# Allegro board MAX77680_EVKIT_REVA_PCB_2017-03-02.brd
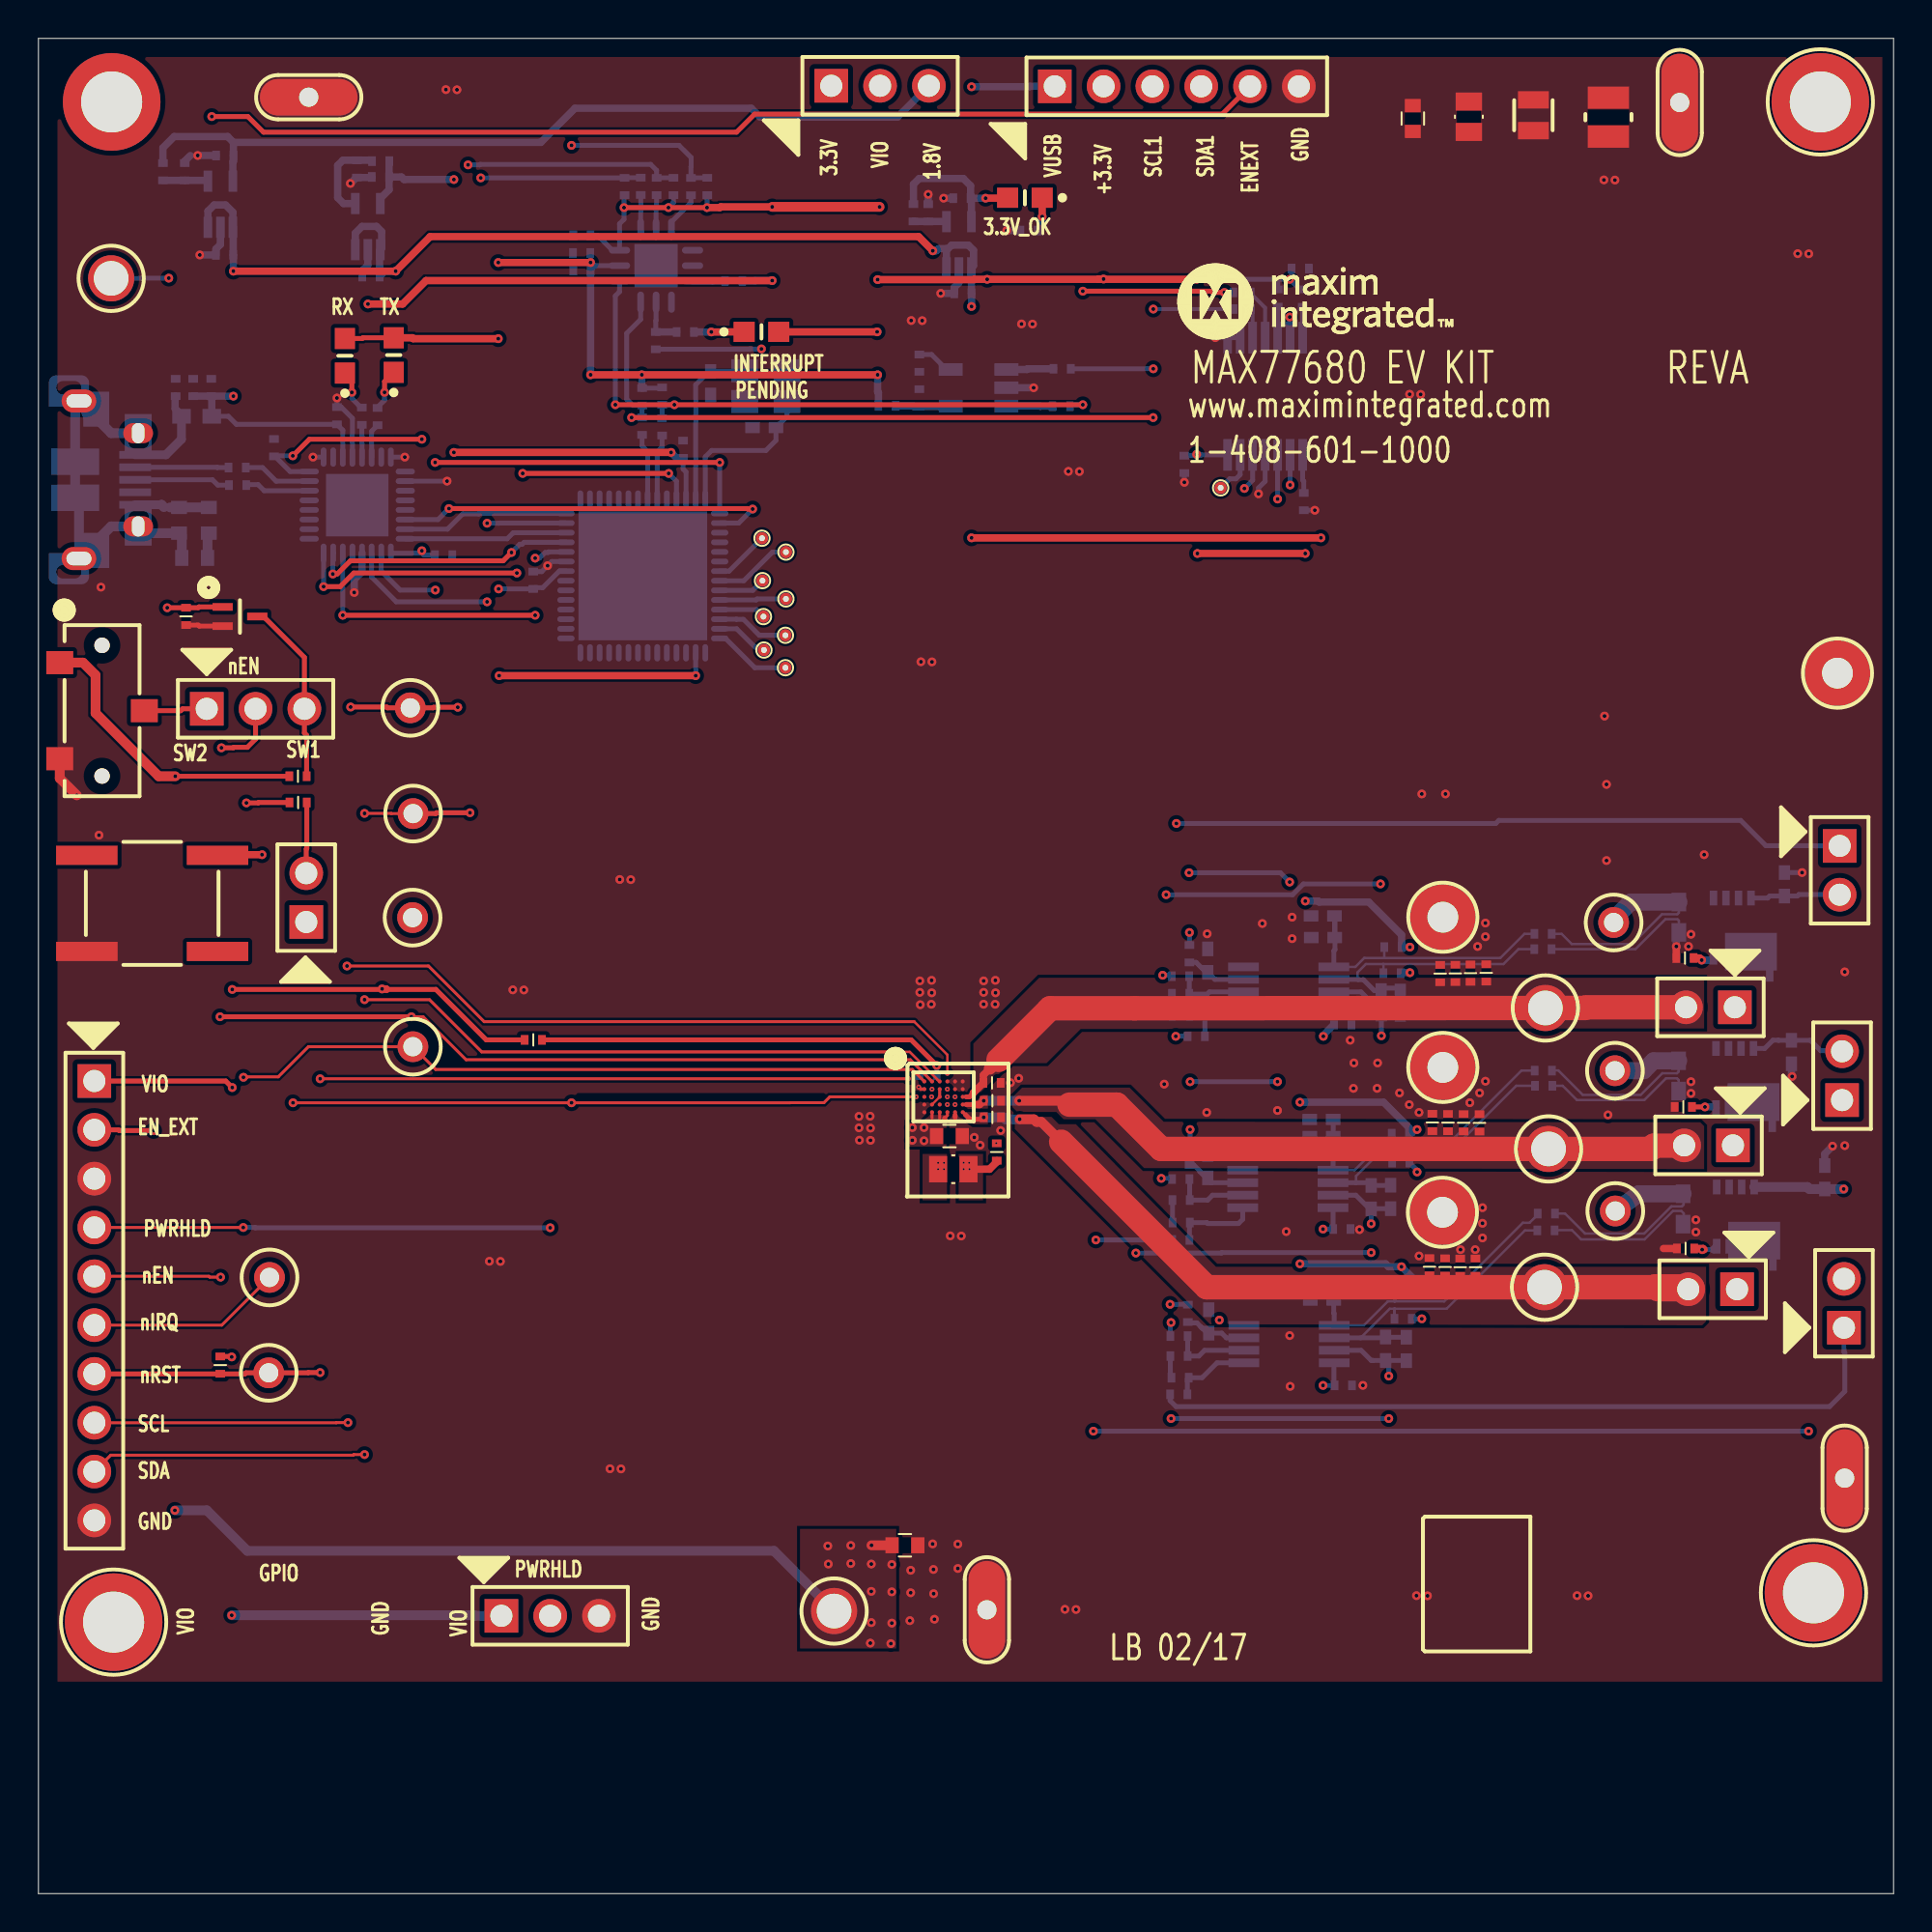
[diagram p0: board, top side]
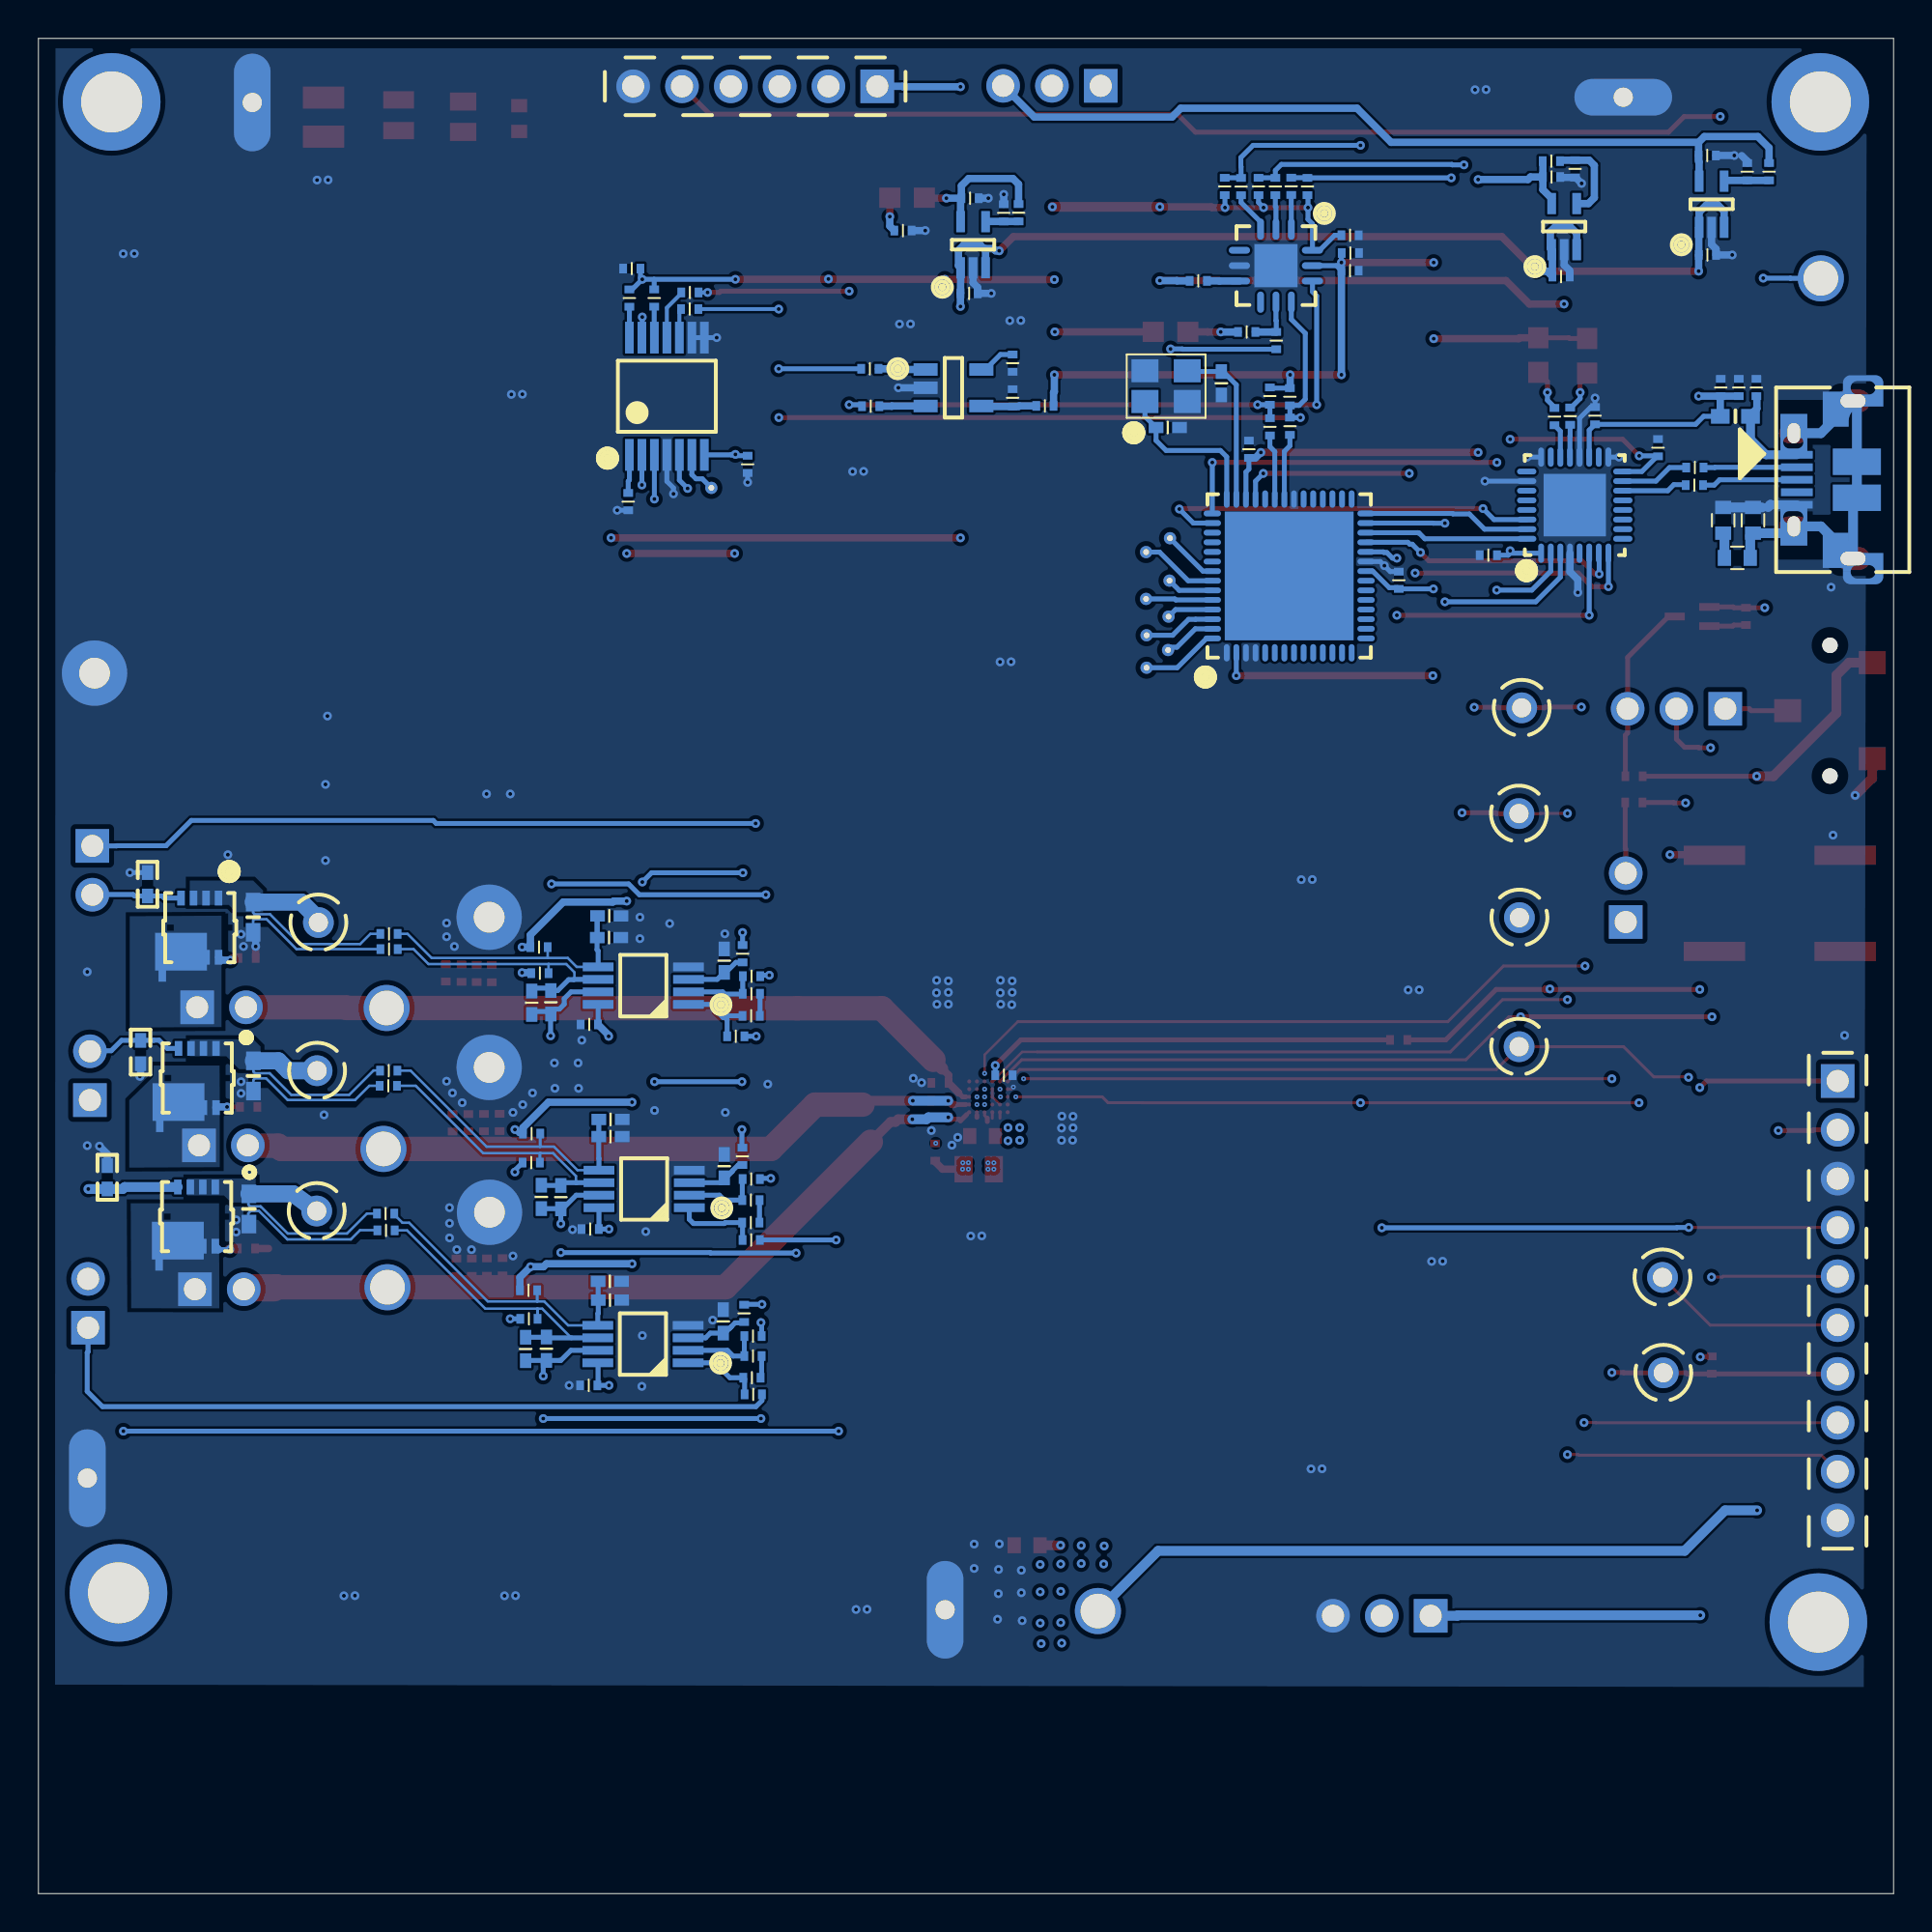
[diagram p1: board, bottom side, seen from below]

Outline 96.52 x 96.52 mm; copper layers: TOP, INTERNAL2, INTERNAL3, BOTTOM. Coordinates in mm from the lower left corner of the outline.
Outline path: 0,96.52 0,0 96.52,0 96.52,96.52 0,96.52

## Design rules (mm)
constraint set DEFAULT: min track width 0.102
net group NIRQ: nets NIRQ UNNAMED_4_EKRESSMD_I87_1
net group NIRQ1: nets NIRQ1 UNNAMED_4_EKRESSMD_I190_2
net group UNNAMED_4_10103592-0001LF_I2_2: nets UNNAMED_4_10103592-0001LF_I2_2 UNNAMED_4_EKRESSMD_I15_2
net group UNNAMED_4_10103592-0001LF_I2_3: nets UNNAMED_4_10103592-0001LF_I2_3 UNNAMED_4_EKRESSMD_I16_2
net group UNNAMED_4_10103592-0001LF_I2_SHIELD10: nets UNNAMED_4_10103592-0001LF_I2_SHIELD10 UNNAMED_4_EKCAPNP_I29_1
net group UNNAMED_4_EKRESSMD_I17_1: nets UNNAMED_4_EKRESSMD_I17_1 UNNAMED_4_EKRESSMD_I17_2
net group UNNAMED_4_EKRESSMD_I18_1: nets UNNAMED_4_EKRESSMD_I18_1 UNNAMED_4_EKRESSMD_I18_2
net group VUSB: nets UNNAMED_4_10103592-0001LF_I2_1 VUSB
net group SCL: nets SCL SDA UNNAMED_4_EKRESSMD_I153_1 UNNAMED_4_EKRESSMD_I154_1 UNNAMED_4_EKRESSMD_I171_2 VIO
net group SCL1: nets SCL1 UNNAMED_4_EKRESSMD_I109_1 UNNAMED_6_24AA02_I452_SCL
net group SDA1: nets SDA1 UNNAMED_4_EKRESSMD_I113_1 UNNAMED_6_24AA02_I452_SDA

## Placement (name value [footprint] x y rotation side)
C1  22UF  [CAPC1608X90L]  47.4 39.41 0 top
C2  0.01UF  [CAPC1005X50L]  75.33 47.9 270 top
C4  3300PF  [0402]  49.86 38.58 270 top
C6  10UF  [CAPC1005X50L]  49.63 40.39 180 top
C8  10UF  [CAPC1005X50L]  49.63 41.25 180 top
C9  10UF  [CAPC1005X50L]  49.61 42.18 180 top
C12  1UF  [CAPC1005X50L]  46.29 42.57 0 bottom
C14  0.1UF  [CAPC1005X50L]  45.83 77.82 270 bottom
C19  OPEN  [CAPC1005X50L]  72.93 47.87 270 top
C20  10UF  [CAPC1005X50L]  72.53 40.12 270 top
C21  OPEN  [CAPC1005X50L]  73.72 47.88 270 top
C22  OPEN  [CAPC1005X50L]  73.34 40.11 270 top
C24  OPEN  [CAPC1005X50L]  72.37 32.61 270 top
C26  OPEN  [CAPC1005X50L]  73.19 32.6 270 top
C27  0.1UF  [CAPC1005X50L]  74.51 47.89 270 top
C28  0.1UF  [CAPC1005X50L]  74.15 40.1 270 top
C29  0.1UF  [CAPC1005X50L]  73.97 32.59 270 top
C30  22UF  [CAPC1608X90L]  45.08 18.12 0 top
C31  0.01UF  [CAPC1005X50L]  74.97 40.1 270 top
C32  0.01UF  [CAPC1005X50L]  74.77 32.59 270 top
C108  0.1UF  [CAPC1005X50L]  15.53 76.89 270 bottom
C110  1UF  [CAPC1005X50L]  9.68 85.26 0 bottom
C111  1UF  [CAPC1005X50L]  9.69 90.43 0 bottom
C112  1UF  [CAPC1005X50L]  17.3 84.13 0 bottom
C113  1UF  [CAPC1005X50L]  17.8 89.31 0 bottom
C114  0.47UF  [CAPC1608X90L]  8.86 71.45 90 bottom
C115  1UF  [CAPC1005X50L]  28.28 84.44 0 bottom
C118  1UF  [CAPC1005X50L]  48.1 83.26 0 bottom
C120  1UF  [CAPC1005X50L]  28.28 86.28 0 bottom
C150  0.1UF  [CAPC1005X50L]  25.74 68.33 90 bottom
C151  0.1UF  [CAPC1005X50L]  33.54 75.15 90 bottom
C152  15PF  [0402#2]  37.76 76.28 0 bottom
C153  15PF  [0402#2]  34.97 78.58 90 bottom
C154  4.7UF  [CAPC1005X50L]  8.05 78.36 270 bottom
C155  0.1UF  [CAPC1005X50L]  7.14 78.36 90 bottom
C156  0.1UF  [CAPC1005X50L]  12.26 75.23 270 bottom
C157  0.1UF  [CAPC1005X50L]  28.26 85.36 0 bottom
C158  1UF  [CAPC1005X50L]  48.05 88.21 0 bottom
C159  0.1UF  [CAPC1005X50L]  21.08 69.63 0 bottom
C200  4700PF  [0402#2]  60.84 48.54 270 bottom
C201  1000PF  [CAPC1005X50L]  59.43 46.82 180 bottom
C202  0.1UF  [CAPC1005X50L]  67.86 45.22 0 bottom
C203  18PF  [0402#2]  69.86 46.37 90 bottom
C204  18PF  [0402#2]  66.83 49.74 0 bottom
C206  1000PF  [CAPC1005X50L]  59.45 36.08 180 bottom
C207  0.1UF  [CAPC1005X50L]  67.81 34.57 0 bottom
C208  18PF  [0402#2]  66.76 39.38 0 bottom
C209  18PF  [0402#2]  70.35 36.25 90 bottom
C211  1000PF  [CAPC1005X50L]  59.34 27.97 180 bottom
C212  0.1UF  [CAPC1005X50L]  67.89 26.44 0 bottom
C213  18PF  [0402#2]  70.09 28.35 90 bottom
C214  18PF  [0402#2]  66.78 30.88 0 bottom
C221  0.1UF  [CAPC1005X50L]  65.65 84.55 180 bottom
C222  0.1UF  [CAPC1005X50L]  59.62 74.36 90 bottom
C223  0.1UF  [CAPC1005X50L]  65.83 72.42 90 bottom
C239  1UF  [CAPC1005X50L]  85.67 48.67 0 top
C240  1UF  [CAPC1005X50L]  85.58 40.93 0 top
C241  1UF  [CAPC1005X50L]  85.7 33.56 0 top
C248  4700PF  [0402#2]  60.84 37.85 270 bottom
C250  4700PF  [0402#2]  60.89 29.77 270 bottom
D100  LTST-C190YKT  [LEDC1608X80M]  18.48 80.05 90 top
D101  LTST-C190YKT  [LEDC1608X80M]  15.94 80.01 90 top
D102  LTST-C190CKT  [LEDC1608X80M]  51.32 88.23 180 top
D103  LTST-C190CKT  [LEDC1608X80M]  37.62 81.25 0 top
EN_EXT  N/A  [TP_C240H180]  3.78 84.04 0 top
FB100  220  [0603#2]  8.23 76.86 0 bottom
GND1  N/A  [TP_C340H160]  93.6 63.5 90 top
GND2  MAXIMPAD  [EVK_MAXIMPAD]  49.35 14.77 270 top
GND3  MAXIMPAD  [EVK_MAXIMPAD]  14.06 93.46 0 top
GND4  MAXIMPAD  [EVK_MAXIMPAD]  85.39 93.19 270 top
GND5  N/A  [TP_C340H160]  73.05 35.45 0 top
GND6  N/A  [TP_C340H160]  73.07 42.98 0 top
GND7  N/A  [TP_C340H160]  73.07 50.8 0 top
GND8  MAXIMPAD  [EVK_MAXIMPAD]  93.98 21.61 90 top
J2  PBC10SAAN  [SULLINS_PXC10SAAN]  2.91 42.28 270 top
J4  TSW-103-07-T-S  [SAMTEC_TSW-103-07-T-S]  24.09 14.45 0 top
J5  TSW-103-07-T-S  [SAMTEC_TSW-103-07-T-S]  8.76 61.64 0 top
J6  10103592-0001LF  [FCI_10103592-0001LF]  2.11 73.56 90 bottom
J8  TSW-102-07-T-S  [SAMTEC_TSW-102-07-X-S]  13.93 50.55 90 top
J100  PBC06SAAN  [SULLINS_PXC06SAAN]  52.88 94.03 0 top
J101  TSW-103-07-T-S  [SAMTEC_TSW-103-07-T-S]  41.25 94.06 0 top
J200  TSW-102-07-T-S  [SAMTEC_TSW-102-07-X-S]  93.72 54.51 270 top
J201  TSW-102-07-T-S  [SAMTEC_TSW-102-07-X-S]  88.26 46.11 180 top
J202  TSW-102-07-T-S  [SAMTEC_TSW-102-07-X-S]  93.84 41.28 90 top
J203  TSW-102-07-T-S  [SAMTEC_TSW-102-07-X-S]  88.16 38.93 180 top
J204  TSW-102-07-T-S  [SAMTEC_TSW-102-07-X-S]  93.94 29.44 90 top
J205  TSW-102-07-T-S  [SAMTEC_TSW-102-07-X-S]  88.38 31.44 180 top
L1  1.5UH  [0805]  47.6 37.69 180 top
L2  0.47UH  [0603]  71.51 92.35 90 top
L3  2.2UH  [0805]  74.42 92.45 90 top
L4  2.2UH  [IND_2016]  77.78 92.53 90 top
L5  2.2UH  [IND_2520]  81.69 92.43 90 top
NEN  N/A  [TP_180P120D460H]  19.47 50.78 0 top
NIRQ  N/A  [TP_180P120D460H]  12.02 32.06 0 top
NOREF  -  []  49.43 150.22 0 top
NOREF#2  -  []  61.29 82.75 0 top
NOREF#3  -  [unnamed#2]  92.35 15.65 0 top
NOREF#4  -  [unnamed#2]  3.81 93.22 0 top
NOREF#5  -  []  -23.98 89.1 0 top
NOREF#6  -  [unnamed#2]  92.71 93.22 0 top
NOREF#7  -  []  108.1 89.1 0 top
NOREF#8  -  [unnamed#2]  3.91 14.12 0 top
NOREF#9  -  []  108.1 -9.96 0 top
NOREF#10  -  []  12.75 1.73 0 top
NRST  N/A  [TP_180P120D460H]  11.98 27.09 0 top
PO0  N/A  [TP_C25H12]  37.65 70.52 90 top
PO1  N/A  [TP_C25H12]  38.89 69.8 90 top
PO2  N/A  [TP_C25H12]  37.67 68.31 90 top
PO3  N/A  [TP_C25H12]  38.89 67.36 90 top
PO4  N/A  [TP_C25H12]  37.72 66.44 90 top
PO5  N/A  [TP_C25H12]  38.86 65.47 90 top
PO6  N/A  [TP_C25H12]  37.75 64.7 90 top
PO7  N/A  [TP_C25H12]  38.86 63.78 90 top
PWRHLD  N/A  [TP_180P120D460H]  19.48 44.06 0 top
Q1  FDY300NZ  [SOT50P160X90-3M]  10.48 66.44 0 top
Q200  IRFHM8337TRPBF  [TRAN_IRF_PQFN8_SINGLE_B]  88.13 50.26 270 bottom
Q201  IRFHM8337TRPBF  [TRAN_IRF_PQFN8_SINGLE_B]  88.26 42.43 270 bottom
Q202  IRFHM8337TRPBF  [TRAN_IRF_PQFN8_SINGLE_B]  88.29 35.22 270 bottom
R1  100K  [RESC1005X50L]  7.61 89.59 90 bottom
R2  10K  [0402]  13.5 58.13 180 top
R3  100K  [RESC1005X50L]  7.68 66.45 270 top
R10  10K  [0402]  9.46 27.5 270 top
R14  100K  [RESC1005X50L]  34.8 88.82 270 bottom
R16  150  [0402]  13.51 56.77 0 top
R17  0  [RESC1005X50L]  25.75 44.42 180 top
R100  4.7K  [RESC1005X50L]  32.45 77.91 90 bottom
R103  22  [RESC1005X50L]  10.36 73.28 0 bottom
R107  2.2K  [RESC1005X50L]  33.04 88.82 90 bottom
R108  2.2K  [RESC1005X50L]  30.5 88.82 90 bottom
R109  100  [RESC1005X50L]  16.83 76.87 90 bottom
R110  470  [0402]  51.54 86.52 180 bottom
R111  100  [RESC1005X50L]  17.64 76.84 90 bottom
R115  100K  [RESC1005X50L]  8.99 78.36 90 bottom
R118  4.7K  [RESC1005X50L]  31.41 77.88 90 bottom
R122  1M  [RESC1608X90L]  7.32 71.45 90 bottom
R123  22  [RESC1005X50L]  10.34 74.19 0 bottom
R135  0  [RESC1005X50L]  31.34 88.83 90 bottom
R136  0  [RESC1005X50L]  32.16 88.82 90 bottom
R142  0  [RESC1608X90L]  8.13 69.49 0 bottom
R143  0  [RESC1005X50L]  36.17 83.91 180 bottom
R148  0  [RESC1005X50L]  32.45 76.31 90 bottom
R150  22  [RESC1005X50L]  33.95 88.81 90 bottom
R152  0  [RESC1005X50L]  32.12 80.8 90 bottom
R155  0  [RESC1005X50L]  31.41 76.34 90 bottom
R156  105K  [0402]  17.81 90.14 180 bottom
R157  100K  [RESC1005X50L]  16.57 89.73 270 bottom
R158  169K  [0402]  45.53 87.45 270 bottom
R159  100K  [RESC1005X50L]  46.29 87.45 90 bottom
R160  47.5K  [0402]  6.48 89.59 270 bottom
R161  470  [0402]  33.66 81.25 180 bottom
R162  0  [RESC1005X50L]  53.26 79.33 180 bottom
R163  0  [RESC1005X50L]  44.15 77.4 180 bottom
R164  0  [RESC1005X50L]  53.22 77.39 0 bottom
R165  0  [RESC1005X50L]  45.83 79.63 270 bottom
R201  100  [0402]  59.44 45.67 0 bottom
R202  680  [0402]  59.42 47.73 180 bottom
R203  20K  [0402]  59.88 48.9 270 bottom
R204  0  [RESC1005X50L]  60.24 44.6 180 bottom
R205  4.99K  [0402#2]  70.85 46.35 90 bottom
R206  4.99K  [0402#2]  66.82 50.86 0 bottom
R207  1K  [RESC1005X50L]  78.28 49.93 0 bottom
R208  1K  [RESC1005X50L]  78.28 49.14 0 bottom
R210  1M  [0402#2]  90.84 52.51 270 bottom
R211  1  [0603#2]  85.35 50.8 270 bottom
R214  100K  [RESC1005X50L]  65.78 83.01 90 bottom
R222  100  [0402]  59.46 34.91 0 bottom
R223  680  [0402]  59.43 37.17 180 bottom
R224  20K  [0402]  59.89 38.36 270 bottom
R225  0  [RESC1005X50L]  59.44 34.01 180 bottom
R226  4.99K  [0402#2]  66.75 40.28 0 bottom
R228  4.99K  [0402#2]  69.34 36.23 90 bottom
R229  1K  [RESC1005X50L]  78.3 42.82 0 bottom
R230  1K  [RESC1005X50L]  78.32 42.03 0 bottom
R231  1M  [0402#2]  91.21 43.78 90 bottom
R233  1  [0603#2]  85.34 42.54 270 bottom
R235  100  [0402]  59.4 26.84 0 bottom
R236  680  [0402]  59.34 29 180 bottom
R237  20K  [0402]  59.8 30.19 270 bottom
R238  0  [RESC1005X50L]  59.33 25.97 180 bottom
R239  4.99K  [0402#2]  71.17 28.33 90 bottom
R240  4.99K  [0402#2]  66.79 31.86 0 bottom
R242  1K  [RESC1005X50L]  78.46 35.38 0 bottom
R243  1K  [RESC1005X50L]  78.44 34.5 0 bottom
R244  1M  [0402#2]  92.94 37.27 270 bottom
R245  1  [0603#2]  85.57 35.62 270 bottom
R283  100K  [RESC1005X50L]  64.48 83.01 270 bottom
R293  470K  [0402]  70.47 49.24 0 bottom
R294  649K  [0402]  70.43 47.89 180 bottom
R295  470K  [0402]  70.86 39.54 0 bottom
R296  649K  [0402]  70.88 38.03 180 bottom
R297  470K  [0402]  71.02 31.39 0 bottom
R298  649K  [0402]  71 29.9 180 bottom
R305  0  [RESC1005X50L]  62.63 82.44 0 bottom
R306  0  [RESC1005X50L]  62.62 83.3 0 bottom
SBB0  N/A  [TP_C240H180]  78.4 46.08 0 top
SBB1  N/A  [TP_C240H180]  78.57 38.74 0 top
SBB2  N/A  [TP_C240H180]  78.36 31.55 0 top
SCL  N/A  [TP_180P120D460H]  19.35 61.69 0 top
SDA  N/A  [TP_180P120D460H]  19.49 56.19 0 top
SW1  EVQ-Q2K03W  [SW_EVQ-Q2X03W]  5.92 51.52 180 top
SW2  CL-SB-12B-11  [SW_CL-SB-12B-1X]  3.31 61.54 0 top
TP1  N/A  [TP_C25H12]  61.51 73.14 0 top
U1  MAX77680  [BGA30C40P6X5_275X215X69M]  47.09 41.45 0 top
U100  MAXQ2000-RBX+  [QFN50P800X800X80-57M]  31.45 68.55 90 bottom
U101  FT232RQ  [QFN50P500X500X100-33V2M]  16.59 72.24 90 bottom
U102  MAX8512EXK  [SOT65P210X110-5M]  47.89 85.79 90 bottom
U103  MAX8512EXK  [SOT65P210X110-5M]  9.47 87.89 90 bottom
U104  MAX8512EXK  [SOT65P210X110-5M]  17.14 86.73 90 bottom
U107  MAX3395EETC  [QFN80P400X400X80-13M]  32.13 84.7 270 bottom
U108  24AA02T-I/OT  [SOT95P280X145-5M]  48.91 78.35 180 bottom
U200  MAX44251AUA+  [SOP65P490X110-8M]  65.05 47.24 0 bottom
U201  MAX44251AUA+  [SOP65P490X110-8M]  65.01 36.66 0 bottom
U202  MAX44251AUA+  [SOP65P490X110-8M]  65.07 28.59 0 bottom
U205  MAX5815AAUD+  [SOP65P640X120-14M]  63.82 77.9 90 bottom
VIL_SBB0  N/A  [TP_180P120D460H]  81.95 50.52 0 top
VIL_SBB1  N/A  [TP_180P120D460H]  82.02 42.81 0 top
VIL_SBB2  N/A  [TP_180P120D460H]  82.04 35.51 0 top
VSYS  N/A  [TP_C240H180]  41.4 14.7 0 top
Y101  16MHZ  [XTAL320X250X070M]  37.85 78.43 180 bottom

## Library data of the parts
C1 C30 = EK_CAP_NP: part number: EK_CAP_NP_0603_FF-CAPC1608X90L,22UF,20-0022U-A48
C2 C31 C32 = EK_CAP_NP: part number: EK_CAP_NP_0402_FF-CAPC1005X50L,0.01UF,20-00U01-B8
C4 = CAP_NP: alternate symbols: 0402_NOSILK,CAPC1005X50L; part number: CAP_NP_0402CAP-0402,3300PF,20-3300P-04
C6 C8 C9 C20 = EK_CAP_NP: part number: EK_CAP_NP_0402_FF-CAPC1005X50L,10UF,20-0010U-B65
C12 C110-C113 C115 C118 C120 C158 C239-C241 = EK_CAP_NP: part number: EK_CAP_NP_0402_FF-CAPC1005X50L,1UF,20-0001U-B65
C14 C156 C157 = EK_CAP_NP: part number: EK_CAP_NP_0402_FF-CAPC1005X50L,0.1UF,20-000U1-12; signal model: DEFAULT_CAPACITOR_100000pF_2_1
C19 C21 C22 C24 C26 = EK_CAP_NP: alternate symbols: 0402,0402_NOSILK; part number: EK_CAP_NP_0402_FF-CAPC1005X50L,OPEN,N/A
C27-C29 = EK_CAP_NP: part number: EK_CAP_NP_0402_FF-CAPC1005X50L,0.1UF,20-000U1-33
C108 C150 C151 C155 C159 C202 C207 C212 C221-C223 = EK_CAP_NP: part number: EK_CAP_NP_0402_FF-CAPC1005X50L,0.1UF,20-000U1-12
C114 = EK_CAP_NP: part number: EK_CAP_NP_0603_FF-CAPC1608X90L,0.47UF,20-00U47-16; signal model: DEFAULT_CAPACITOR_470000pF_2_1
C152 C153 = CAP_NP: alternate symbols: 0402_NOSILK,CAPC1005X50L; part number: CAP_NP_0402CAP-0402,15PF,20-0015P-F3
C154 = EK_CAP_NP: part number: EK_CAP_NP_0402_FF-CAPC1005X50L,4.7UF,20-004U7-33A; signal model: DEFAULT_CAPACITOR_4.7e+06pF_2_1
C200 C248 C250 = CAP_NP: alternate symbols: (0402_NOSILK); part number: CAP_NP_0402CAP-0402,4700PF,20-4700P-A0Z
C201 C206 C211 = EK_CAP_NP: part number: EK_CAP_NP_0402_FF-CAPC1005X50L,1000PF,20-1000P-E7
C203 C204 C208 C209 C213 C214 = CAP_NP: alternate symbols: 0402_NOSILK,CAPC1005X50L; part number: CAP_NP_0402CAP-0402,18PF,20-0018P-27
D100 D101 = LED: part number: LED_LEDC1608X80M-LEDC1608X80M,LTST-C190YKT,30-LTSTC190YKT-00
D102 D103 = LED: part number: LED_LEDC1608X80M-LEDC1608X80M,LTST-C190CKT,30-LTSTC190CKT-00
EN_EXT SBB0-SBB2 VSYS = TP: alternate symbols: TP_C340H160L; part number: TP_TP-TP_C240H180,N/A,02-TPMINI5010-00
FB100 = INDUCT: alternate symbols: (0603_NOSILK); part number: INDUCT_0603-0603,220,50-00220-SM12A; signal model: DEFAULT_INDUCTOR_220.000000nH_1_2
GND1 GND5-GND7 = TP: alternate symbols: TP_C340H160L; part number: TP_TP-TP_C340H160,N/A,02-TPMINI5011-00
GND2-GND4 GND8 = EVK_MAXIMPAD: alternate symbols: EVK_MAXIMPAD_ALT; part number: EVK_MAXIMPAD_MISC-EVK_MAXIMPAD,MAXIMPAD,01-9020BUSS20AWG-00
J2 = HEADER_10P: part number: HEADER_10P_TH-SULLINS_PXC10SAAN,PBC10SAAN,01-PBC10SAAN10P-21
J4 J5 J101 = HEADER_3P: part number: HEADER_3P_SIP-SAMTEC_TSW-103-07-T-S,TSW-103-07-T-S,01-TSW10307TS3P-17
J6 = 10103592-0001LF: part number: 10103592-0001LF_SMT-FCI_10103592-0001LF,10103592-0001LF,01-101035920001LF5P-26
J8 J200-J205 = HEADER_2P: part number: HEADER_2P_TH-SAMTEC_TSW-102-07-X-S,TSW-102-07-T-S,01-TSW10207TS2P-17
J100 = HEADER_6P: part number: HEADER_6P_TH-SULLINS_PXC06SAAN,PBC06SAAN,01-PBC06SAAN6P-21
L1 = EVKIT_INDUCT: alternate symbols: INDC2012X145L; part number: EVKIT_INDUCT_IND_0805-0805,1.5UH,50-001U5-0LP
L2 = INDUCT: alternate symbols: 0603_NOSILK,INDC1608X90L; part number: INDUCT_0603-0603,0.47UH,50-00U47-0DK
L3 = EVKIT_INDUCT: alternate symbols: INDC2012X145L; part number: EVKIT_INDUCT_IND_0805-0805,2.2UH,50-002U2-0LM
L4 = EVKIT_INDUCT: alternate symbols: INDC2016X100L; part number: EVKIT_INDUCT_IND_0806-IND_2016,2.2UH,50-002U2-0LO
L5 = EVKIT_INDUCT: alternate symbols: INDC2520X120L; part number: EVKIT_INDUCT_2520-IND_2520,2.2UH,50-002U2-0LN
NEN NIRQ NRST PWRHLD SCL SDA = TP: part number: TP_TP-TP_180P120D460H,N/A,02-TPMINI5002-00
PO0-PO7 TP1 = TP: part number: TP_TP-TP_C25H12,N/A,N/A
Q1 = TRAN_NCH_3P: part number: TRAN_NCH_3P_SC89_TRENCH-SOT50P160X90-3M,FDY300NZ,90-FDY300NZ-28
Q200-Q202 = TRAN_NCH_8P: part number: TRAN_NCH_8P_PQFN8-TRAN_IRF_PQFN8_SINGLE_B,IRFHM8337TRPBF,90-IRFHM8337-10
R1 R3 R14 R157 R159 R214 R283 = EK_RES_SMD: part number: EK_RES_SMD_0402_FF-RESC1005X50L,100K,80-0100K-23
R2 R10 = RES: alternate symbols: 0402_NOSILK,RESC1005X50L,RES0402-NOT_FOR_TEST; part number: RES_0402RES-0402,10K,80-0010K-23
R16 = RES: alternate symbols: (0402_NOSILK,RESC1005X50L); part number: RES_0402RES-0402,150,80-0150R-23
R17 R204 R225 R238 R305 R306 = EK_RES_SMD: part number: EK_RES_SMD_0402_FF-RESC1005X50L,0,80-0000R-26
R100 R118 = EK_RES_SMD: part number: EK_RES_SMD_0402_FF-RESC1005X50L,4.7K,80-004K7-23; signal model: DEFAULT_RESISTOR_4700OHM_2_1
R103 R123 = EK_RES_SMD: part number: EK_RES_SMD_0402_FF-RESC1005X50L,22,80-0022R-23; signal model: DEFAULT_RESISTOR_22.000000OHM_1_2
R107 R108 = EK_RES_SMD: part number: EK_RES_SMD_0402_FF-RESC1005X50L,2.2K,80-002K2-23; signal model: DEFAULT_RESISTOR_470.000000OHM_1_2
R109 R111 = EK_RES_SMD: part number: EK_RES_SMD_0402_FF-RESC1005X50L,100,80-0100R-23; signal model: DEFAULT_RESISTOR_100.000000OHM_2_1
R110 R161 = RES: alternate symbols: (0402_NOSILK,RESC1005X50L); part number: RES_0402RES-0402,470,80-0470R-23
R115 = EK_RES_SMD: part number: EK_RES_SMD_0402_FF-RESC1005X50L,100K,80-0100K-23; signal model: DEFAULT_RESISTOR_100000OHM_1_2
R122 = EK_RES_SMD: part number: EK_RES_SMD_0603_FF-RESC1608X90L,1M,80-0001M-19; signal model: DEFAULT_RESISTOR_0.001OHM_2_1
R135 R136 R148 R152 R155 R162-R165 = EK_RES_SMD: part number: EK_RES_SMD_0402_FF-RESC1005X50L,0,80-0000R-26; signal model: DEFAULT_RESISTOR_22.000000OHM_2_1
R142 = EK_RES_SMD: part number: EK_RES_SMD_0603_FF-RESC1608X90L,0,80-0000R-27; signal model: DEFAULT_RESISTOR_0.001OHM_2_1
R143 = EK_RES_SMD: part number: EK_RES_SMD_0402_FF-RESC1005X50L,0,80-0000R-26; signal model: DEFAULT_RESISTOR_0.001OHM_1_2
R150 = EK_RES_SMD: part number: EK_RES_SMD_0402_FF-RESC1005X50L,22,80-0022R-23; signal model: DEFAULT_RESISTOR_22.000000OHM_2_1
R156 = RES: alternate symbols: (0402_NOSILK,RESC1005X50L); part number: RES_0402RES-0402,105K,80-0105K-18
R158 = RES: alternate symbols: (0402_NOSILK,RESC1005X50L); part number: RES_0402RES-0402,169K,80-0169K-23
R160 = RES: alternate symbols: (0402_NOSILK,RESC1005X50L); part number: RES_0402RES-0402,47.5K,80-047K5-23
R201 R222 R235 = RES: alternate symbols: 0402_NOSILK,RESC1005X50L,RES0402-NOT_FOR_TEST; part number: RES_0402RES-0402,100,80-0100R-23
R202 R223 R236 = RES: alternate symbols: (0402_NOSILK,RESC1005X50L); part number: RES_0402RES-0402,680,80-0680R-23
R203 R224 R237 = RES: alternate symbols: 0402_NOSILK,RESC1005X50L,RES0402-NOT_FOR_TEST; part number: RES_0402RES-0402,20K,80-0020K-23
R205 R206 R226 R228 R239 R240 = RES: alternate symbols: (0402_NOSILK,RESC1005X50L); part number: RES_0402RES-0402,4.99K,80-04K99-23
R207 R208 R229 R230 R242 R243 = EK_RES_SMD: part number: EK_RES_SMD_0402_FF-RESC1005X50L,1K,80-0001K-23
R210 R231 R244 = RES: alternate symbols: (0402_NOSILK,RESC1005X50L); part number: RES_0402RES-0402,1M,80-0001M-23
R211 R233 R245 = RES: alternate symbols: (0603_NOSILK); part number: RES_0603RES-0603,1,80-0001R-24
R293 R295 R297 = RES: alternate symbols: (0402_NOSILK,RESC1005X50L); part number: RES_0402RES-0402,470K,80-0470K-23
R294 R296 R298 = RES: alternate symbols: 0402_NOSILK,RESC1005X50L; part number: RES_0402RES-0402,649K,80-0649K-AA18
SW1 = EVQ-Q2XXXX: part number: EVQ-Q2XXXX_SMT-SW_EVQ-Q2X03W,EVQ-Q2K03W,11-EVQQ2K03W-00
SW2 = CL-SB-12B-1X: part number: CL-SB-12B-1X_SMD-SW_CL-SB-12B-1X,CL-SB-12B-11,11-CLSB12B11-00
U1 = EK_MAX77680: alternate symbols: BGA30C40P6X5_275X215X69L; part number: EK_MAX77680_WLP30-BGA30C40P6X5_275X215X69M,MAX77680,N/A
U100 = MAXQ2000: part number: MAXQ2000_TQFN56-EP-QFN50P800X800X80-57M,MAXQ2000-RBX+,10-MAXQ2000RBX-T
U101 = FT232RQ: part number: FT232RQ_QFN32-EP-QFN50P500X500X100-33V2M,FT232RQ,10-FT232RQ-G
U102-U104 = MAX8512: part number: MAX8512_SC70-SOT65P210X110-5M,MAX8512EXK,10-MAX8512EXK-X
U107 = MAX3395E: part number: MAX3395E_TQFN-QFN80P400X400X80-13M,MAX3395EETC,10-MAX3395EETC-T
U108 = 24AA02: part number: 24AA02_SOT23-5-SOT95P280X145-5M,24AA02T-I/OT,10-24AA02TIOT-U
U200-U202 = MAX44251: part number: MAX44251_SPLIT_UMAX8-SOP65P490X110-8M,MAX44251AUA+,10-MAX44251AUA-U
U205 = MAX5815: part number: MAX5815_TSSOP14-SOP65P640X120-14M,MAX5815AAUD+,10-MAX5815AAUD-U
VIL_SBB0-VIL_SBB2 = TP: part number: TP_TP-TP_180P120D460H,N/A,02-TPMINI5000-00
Y101 = XTAL: part number: XTAL_XTAL320X250X070M-XTAL320X250X070M,16MHZ,60-0016M-26A

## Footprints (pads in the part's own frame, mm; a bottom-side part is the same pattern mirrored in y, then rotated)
0402
  rect 0.4x0.5 smd: 1(-0.45,0) 2(0.45,0)
0402#2
  rect 0.762x0.584 smd: 1(-0.61,0) 2(0.61,0)
0603
  rect 0.69x0.83 smd: 1(-0.67,0) 2(0.67,0)
0603#2
  rect 0.965x0.762 smd: 1(-0.787,0) 2(0.787,0)
0805
  rect 0.94x1.37 smd: 1(-0.79,0) 2(0.79,0)
BGA30C40P6X5_275X215X69M
  round 0.21 smd: A1(-1,0.8) A2(-0.6,0.8) A3(-0.2,0.8) A4(0.2,0.8) A5(0.6,0.8) A6(1,0.8) B1(-1,0.4) B2(-0.6,0.4) B3(-0.2,0.4) B4(0.2,0.4) B5(0.6,0.4) B6(1,0.4) C1(-1,0) C2(-0.6,0) C3(-0.2,0) C4(0.2,0) C5(0.6,0) C6(1,0) D1(-1,-0.4) D2(-0.6,-0.4) D3(-0.2,-0.4) D4(0.2,-0.4) D5(0.6,-0.4) D6(1,-0.4) E1(-1,-0.8) E2(-0.6,-0.8) E3(-0.2,-0.8) E4(0.2,-0.8) E5(0.6,-0.8) E6(1,-0.8)
CAPC1005X50L
  rect 0.4x0.5 smd: 1(-0.45,0) 2(0.45,0)
CAPC1608X90L
  rect 0.69x0.83 smd: 1(-0.67,0) 2(0.67,0)
EVK_MAXIMPAD
  oval 5.08x1.905 hole 1: 1(0,0)
FCI_10103592-0001LF
  rect 0.4x1.65 smd: 1(1.3,2.925) 2(0.65,2.925) 3(0,2.925) 4(-0.65,2.925) 5(-1.3,2.925)
  oval 1.2x1.8 hole 0.7x1.3: 6(-4.1,0) 9(4.1,0)
  oval 1.05x1.55 hole 1.05x0.65: 7(-2.425,3.08) 8(2.425,3.08)
  rect 1.375x2.5 smd: 10(0.938,-0.2) 11(-0.938,-0.2)
IND_2016
  rect 0.9x1.6 smd: 1(-0.8,0) 2(0.8,0)
IND_2520
  rect 1.15x2.15 smd: 1(-1.015,0) 2(1.015,0)
LEDC1608X80M
  rect 1.1x1.05 smd: A(0.9,0) K(-0.9,0)
QFN50P500X500X100-33V2M
  oval 1x0.3 smd: 1(-2.5,1.75) 2(-2.5,1.25) 3(-2.5,0.75) 4(-2.5,0.25) 5(-2.5,-0.25) 6(-2.5,-0.75) 7(-2.5,-1.25) 8(-2.5,-1.75) 17(2.5,-1.75) 18(2.5,-1.25) 19(2.5,-0.75) 20(2.5,-0.25) 21(2.5,0.25) 22(2.5,0.75) 23(2.5,1.25) 24(2.5,1.75)
  oval 0.3x1 smd: 9(-1.75,-2.5) 10(-1.25,-2.5) 11(-0.75,-2.5) 12(-0.25,-2.5) 13(0.25,-2.5) 14(0.75,-2.5) 15(1.25,-2.5) 16(1.75,-2.5) 25(1.75,2.5) 26(1.25,2.5) 27(0.75,2.5) 28(0.25,2.5) 29(-0.25,2.5) 30(-0.75,2.5) 31(-1.25,2.5) 32(-1.75,2.5)
  rect 3.25x3.25 smd: 33(0,0)
QFN50P800X800X80-57M
  oval 0.9x0.3 smd: 1(-4,3.25) 2(-4,2.75) 3(-4,2.25) 4(-4,1.75) 5(-4,1.25) 6(-4,0.75) 7(-4,0.25) 8(-4,-0.25) 9(-4,-0.75) 10(-4,-1.25) 11(-4,-1.75) 12(-4,-2.25) 13(-4,-2.75) 14(-4,-3.25) 29(4,-3.25) 30(4,-2.75) 31(4,-2.25) 32(4,-1.75) 33(4,-1.25) 34(4,-0.75) 35(4,-0.25) 36(4,0.25) 37(4,0.75) 38(4,1.25) 39(4,1.75) 40(4,2.25) 41(4,2.75) 42(4,3.25)
  oval 0.3x0.9 smd: 15(-3.25,-4) 16(-2.75,-4) 17(-2.25,-4) 18(-1.75,-4) 19(-1.25,-4) 20(-0.75,-4) 21(-0.25,-4) 22(0.25,-4) 23(0.75,-4) 24(1.25,-4) 25(1.75,-4) 26(2.25,-4) 27(2.75,-4) 28(3.25,-4) 43(3.25,4) 44(2.75,4) 45(2.25,4) 46(1.75,4) 47(1.25,4) 48(0.75,4) 49(0.25,4) 50(-0.25,4) 51(-0.75,4) 52(-1.25,4) 53(-1.75,4) 54(-2.25,4) 55(-2.75,4) 56(-3.25,4)
  rect 6.7x6.7 smd: 57(0,0)
QFN80P400X400X80-13M
  oval 1.1x0.35 smd: 1(-1.9,0.8) 2(-1.9,0) 3(-1.9,-0.8) 7(1.9,-0.8) 8(1.9,0) 9(1.9,0.8)
  oval 0.35x1.1 smd: 4(-0.8,-1.9) 5(0,-1.9) 6(0.8,-1.9) 10(0.8,1.9) 11(0,1.9) 12(-0.8,1.9)
  rect 2.25x2.25 smd: 13(0,0)
RESC1005X50L
  rect 0.4x0.5 smd: 1(-0.45,0) 2(0.45,0)
RESC1608X90L
  rect 0.69x0.83 smd: 1(-0.67,0) 2(0.67,0)
SAMTEC_TSW-102-07-X-S
  rect 1.75x1.75 hole 1.15: 1(0,0)
  round 1.75 hole 1.15: 2(2.54,0)
SAMTEC_TSW-103-07-T-S
  rect 1.75x1.75 hole 1.15: 1(0,0)
  round 1.75 hole 1.15: 2(2.54,0) 3(5.08,0)
SOP65P490X110-8M
  rect 1.6x0.45 smd: 1(-2.35,0.975) 2(-2.35,0.325) 3(-2.35,-0.325) 4(-2.35,-0.975) 5(2.35,-0.975) 6(2.35,-0.325) 7(2.35,0.325) 8(2.35,0.975)
SOP65P640X120-14M
  rect 1.65x0.45 smd: 1(-3.05,1.95) 2(-3.05,1.3) 3(-3.05,0.65) 4(-3.05,0) 5(-3.05,-0.65) 6(-3.05,-1.3) 7(-3.05,-1.95) 8(3.05,-1.95) 9(3.05,-1.3) 10(3.05,-0.65) 11(3.05,0) 12(3.05,0.65) 13(3.05,1.3) 14(3.05,1.95)
SOT50P160X90-3M
  rect 1.05x0.4 smd: 1(-0.9,0.5) 2(-0.9,-0.5) 3(0.9,0)
SOT65P210X110-5M
  rect 1.1x0.45 smd: 1(-1.2,0.65) 2(-1.2,0) 3(-1.2,-0.65) 4(1.2,-0.65) 5(1.2,0.65)
SOT95P280X145-5M
  rect 1.25x0.65 smd: 1(-1.45,0.95) 2(-1.45,0) 3(-1.45,-0.95) 4(1.45,-0.95) 5(1.45,0.95)
SULLINS_PXC06SAAN
  rect 1.75x1.75 hole 1.15: 1(0,0)
  round 1.75 hole 1.15: 2(2.54,0) 3(5.08,0) 4(7.62,0) 5(10.16,0) 6(12.7,0)
SULLINS_PXC10SAAN
  rect 1.75x1.75 hole 1.15: 1(0,0)
  round 1.75 hole 1.15: 2(2.54,0) 3(5.08,0) 4(7.62,0) 5(10.16,0) 6(12.7,0) 7(15.24,0) 8(17.78,0) 9(20.32,0) 10(22.86,0)
SW_CL-SB-12B-1X
  round 0.8 hole 0.9 unplated: (0,3.4) (0,-3.4)
  rect 1.4x1.2 smd: 1(-2.2,2.5) 2(2.2,0) 3(-2.2,-2.5)
SW_EVQ-Q2X03W
  rect 3.2x1 smd: 1(-3.4,-2.5) 2(3.4,-2.5) 3(-3.4,2.5) 4(3.4,2.5)
TP_180P120D460H
  round 1.6 hole 1: 1(0,0)
TP_C25H12
  round 0.635 hole 0.305: 1(0,0)
TP_C240H180
  round 2.4 hole 1.8: 1(0,0)
TP_C340H160
  round 3.4 hole 1.6: 1(0,0)
TRAN_IRF_PQFN8_SINGLE_B
  rect 0.77x0.39 smd: 1(-1.54,0.975) 2(-1.54,0.325) 3(-1.54,-0.325) 4(-1.54,-0.975) 6(1.54,-0.325) 7(1.54,0.325) 8(1.54,0.975)
  custom 0.635x0.635 smd: 5(1.54,-0.975)
unnamed#2
  round 5.08 hole 3.175: (0,0)
XTAL320X250X070M
  rect 1.4x1.2 smd: 1(-1.1,-0.8) 2(1.1,-0.8) 3(1.1,0.8) 4(-1.1,0.8)

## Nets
+1.8V: C111.2 J101.3 R160.1 U103.5
+2.5V: C113.2 C151.1 R156.1 U100.40 U104.5
+3.3V: C115.2 C150.1 C157.2 C158.2 C221.2 C222.2 D100.A D101.A D102.A D103.A J100.2 J101.1 R100.2 R118.2 R158.1 R163.2 R214.2 R283.1 R293.2 R294.1 R295.2 R296.1 R297.2 R298.1 U100.2 U100.22 U102.5 U107.11 U205.7 U205.13(VDDIO)
BST: C4.1 U1.C5
CTSN: U100.39 U101.8
DCDN: U100.25 U101.7
DSRN: U100.24 U101.6
DTRN: U100.28 U101.31
EN_EXT: EN_EXT.1(TP1) J2.2 J100.5 Q1.1 R3.1
GROUND: C1.2 C2.1 C6.1 C8.1 C9.1 C12.1 C14.1 C19.1 C20.1 C21.1 C22.1 C24.1 C26.1 C27.1 C28.1 C29.1 C30.2 C31.1 C32.1 C108.1 C110.1 C111.1 C112.1 C113.1 C114.2 C115.1 C118.1 C120.1 C150.2 C151.2 C152.1 C153.1 C154.1 C155.2 C156.1 C157.1 C158.1 C159.2 C200.1 C202.2 C204.1 C207.2 C208.1 C212.2 C214.1 C221.1 C222.1 C223.1 C239.1 C240.1 C241.1 C248.1 C250.1 GND1.1(TP1) GND2.1 GND3.1 GND4.1 GND5.1(TP1) GND6.1(TP1) GND7.1(TP1) GND8.1 J2.3 J2.10 J4.3 J6.5 J100.6 L2.1 L2.2 L3.1 L3.2 L4.1 L4.2 L5.1 L5.2 Q1.2(S) R1.2 R3.2 R110.2 R115.2 R122.2 R157.2 R159.2 R165.2 R206.1 R208.2 R210.1 R211.2 R226.1 R230.2 R231.1 R233.2 R240.1 R243.2 R244.1 R245.2 SW1.4 SW2.3 U1.A4 U1.A5 U1.A6 U1.B1 U1.B3 U1.B5 U1.B6 U1.C3 U1.D1 U1.D2 U1.E1 U1.E5 U100.1 U100.3 U100.4 U100.23 U100.35 U101.4 U101.17 U101.20 U101.24 U101.26 U101.33 U102.2 U103.2 U104.2 U107.5 U107.13 U108.2 U200.4 U201.4 U202.4 U205.4 U205.8 U205.9 Y101.2 Y101.4
ISET_SBB0: R203.1 U205.2
ISET_SBB1: R224.1 U205.3
ISET_SBB2: R237.1 U205.5
LXA: L1.2 U1.D4
LXB: C4.2 L1.1 U1.D5
MAXQP03: PO3.1(TP1) U100.52
MAXQP05: PO5.1(TP1) U100.54
NEN: J2.5 J5.2 NEN.1(TP1) U1.A2
NIRQ: J2.6 NIRQ.1(TP1) R14.1 R150.2 U1.C2
NIRQ1: PO0.1(TP1) R152.1 U100.49
NRST: J2.7 J8.1 NRST.1(TP1) R10.2 U1.B2
P01: PO1.1(TP1) U100.50
P02: PO2.1(TP1) U100.51
P04: PO4.1(TP1) U100.53
P06: PO6.1(TP1) U100.55
P07: PO7.1(TP1) U100.56
PWRHLD: J2.4 J4.2 PWRHLD.1(TP1) R16.1 U1.A1
RIN: U100.27 U101.3
RTSN: U100.26 U101.32
RXD: U100.43 U101.2
SBB0: C2.2 C9.2 C19.2 C21.2 C27.2 J201.2 SBB0.1(TP1) U1.C6
SBB1: C8.2 C20.2 C22.2 C28.2 C31.2 J203.2 SBB1.1(TP1) U1.D6
SBB2: C6.2 C24.2 C26.2 C29.2 C32.2 J205.2 SBB2.1(TP1) U1.E6
SCL: J2.8 R107.2 R136.2 SCL.1(TP1) U1.B4
SCL1: J100.3 R118.1 R155.2 R162.1 R305.1 U107.9
SDA: J2.9 R108.2 R135.2 SDA.1(TP1) U1.A3
SDA1: J100.4 R100.1 R148.2 R164.2 R306.1 U107.10
TXD: U100.44 U101.30
UNNAMED_1_CL-SB-12B-1X_I99_2: J5.1 SW2.2
UNNAMED_1_EKCAPNP_I69_2: C12.2 R17.1 U1.C4(VIO)
UNNAMED_1_EVQ-Q2XXXX_I7_1: J5.3 Q1.3 R2.1 SW1.1
UNNAMED_1_HEADER2P_I92_2: J8.2 R16.2
UNNAMED_4_10103592-0001LF_I2_1: C155.1 FB100.1 J6.1
UNNAMED_4_10103592-0001LF_I2_2: J6.2 R123.1
UNNAMED_4_10103592-0001LF_I2_3: J6.3 R103.1
UNNAMED_4_10103592-0001LF_I2_SHIELD10: J6.6 J6.7 J6.8 J6.9(SHIELD9) J6.10 J6.11 R122.1 R142.1
UNNAMED_4_CAPNP_I101_2: C153.2 U100.41 Y101.3(P2)
UNNAMED_4_CAPNP_I105_2: C152.2 U100.42 Y101.1
UNNAMED_4_EKCAPNP_I12_1: C156.2 C159.1 U101.1(VCCIO) U101.16
UNNAMED_4_EKCAPNP_I29_1: C114.1 R142.2
UNNAMED_4_EKRESSMD_I15_2: R123.2 U101.15
UNNAMED_4_EKRESSMD_I16_2: R103.2 U101.14
UNNAMED_4_EKRESSMD_I17_1: R111.1 U101.22
UNNAMED_4_EKRESSMD_I17_2: D100.K(B) R111.2
UNNAMED_4_EKRESSMD_I18_1: R109.1 U101.21
UNNAMED_4_EKRESSMD_I18_2: D101.K(B) R109.2
UNNAMED_4_EKRESSMD_I87_1: R150.1 U107.3
UNNAMED_4_EKRESSMD_I109_1: R155.1 U100.36
UNNAMED_4_EKRESSMD_I113_1: R148.1 U100.37
UNNAMED_4_EKRESSMD_I153_1: R135.1 U107.1
UNNAMED_4_EKRESSMD_I154_1: R136.1 U107.2
UNNAMED_4_EKRESSMD_I171_2: R143.2 U107.6
UNNAMED_4_EKRESSMD_I174_1: R156.2 R157.1 U104.4
UNNAMED_4_EKRESSMD_I177_1: R158.2 R159.1 U102.4
UNNAMED_4_EKRESSMD_I190_2: R152.2 R161.2 U107.8
UNNAMED_4_LED_I7_B: D102.K(B) R110.1
UNNAMED_4_LED_I189_B: D103.K(B) R161.1
UNNAMED_4_MAX8512_I5_FB: R1.1 R160.2 U103.4
UNNAMED_6_24AA02_I452_SCL: R162.2 U108.1
UNNAMED_6_24AA02_I452_SDA: R164.1 U108.3
UNNAMED_6_24AA02_I452_VCC: C14.2 R163.1 U108.4
UNNAMED_6_24AA02_I452_WP: R165.1 U108.5(WP)
UNNAMED_6_CAPNP_I21_1: C203.1 R202.2 R205.1 U200.7(OUTB)
UNNAMED_6_CAPNP_I271_2: C208.2 R226.2 R229.1 R295.1 U201.5
UNNAMED_6_CAPNP_I277_1: C209.1 R223.2 R228.1 U201.7(OUTB)
UNNAMED_6_CAPNP_I277_2: C209.2 R228.2 R230.1 R296.2 U201.6
UNNAMED_6_CAPNP_I289_2: C248.2 R224.2 U201.3
UNNAMED_6_CAPNP_I307_2: C214.2 R240.2 R242.1 R297.1 U202.5
UNNAMED_6_CAPNP_I311_1: C213.1 R236.2 R239.1 U202.7(OUTB)
UNNAMED_6_CAPNP_I311_2: C213.2 R239.2 R243.1 R298.2 U202.6
UNNAMED_6_CAPNP_I323_2: C250.2 R237.2 U202.3
UNNAMED_6_CAPNP_I359_2: C200.2 R203.2 U200.3
UNNAMED_6_EKCAPNP_I10_1: C201.1 R202.1 U200.2
UNNAMED_6_EKCAPNP_I10_2: C201.2 R201.1
UNNAMED_6_EKCAPNP_I203_2: C223.2 U205.1
UNNAMED_6_EKCAPNP_I237_2: C239.2 J201.1 Q200.5 Q200.6 Q200.7 Q200.8
UNNAMED_6_EKCAPNP_I261_2: C240.2 J203.1 Q201.5 Q201.6 Q201.7 Q201.8
UNNAMED_6_EKCAPNP_I287_1: C206.1 R223.1 U201.2
UNNAMED_6_EKCAPNP_I287_2: C206.2 R222.1
UNNAMED_6_EKCAPNP_I298_2: C241.2 J205.1 Q202.5 Q202.6 Q202.7 Q202.8
UNNAMED_6_EKCAPNP_I321_1: C211.1 R236.1 U202.2
UNNAMED_6_EKCAPNP_I321_2: C211.2 R235.1
UNNAMED_6_EKRESSMD_I42_1: C204.2 R206.2 R207.1 R293.1 U200.5
UNNAMED_6_EKRESSMD_I42_2: Q200.1 Q200.2 Q200.3(S3) R207.2 R211.1 VIL_SBB0.1(TP1)
UNNAMED_6_EKRESSMD_I43_1: C203.2 R205.2 R208.1 R294.2 U200.6
UNNAMED_6_EKRESSMD_I99_1: R201.2 R204.1 U200.1
UNNAMED_6_EKRESSMD_I99_2: J200.1 R204.2
UNNAMED_6_EKRESSMD_I207_1: R214.1 U205.14
UNNAMED_6_EKRESSMD_I222_2: R283.2 U205.12
UNNAMED_6_EKRESSMD_I273_2: Q201.1 Q201.2 Q201.3(S3) R229.2 R233.1 VIL_SBB1.1(TP1)
UNNAMED_6_EKRESSMD_I278_1: R222.2 R225.1 U201.1
UNNAMED_6_EKRESSMD_I278_2: J202.1 R225.2
UNNAMED_6_EKRESSMD_I306_2: Q202.1 Q202.2 Q202.3(S3) R242.2 R245.1 VIL_SBB2.1(TP1)
UNNAMED_6_EKRESSMD_I313_1: R235.2 R238.1 U202.1
UNNAMED_6_EKRESSMD_I313_2: J204.1 R238.2
UNNAMED_6_EKRESSMD_I450_2: R305.2 U205.10
UNNAMED_6_EKRESSMD_I451_2: R306.2 U205.11
UNNAMED_6_HEADER2P_I444_2: J202.2 Q201.4 R231.2
UNNAMED_6_HEADER2P_I446_2: J204.2 Q202.4 R244.2
UNNAMED_6_MAX5815_I205_OUTD: TP1.1(TP1) U205.6
UNNAMED_6_RESSMD_I28_2: J200.2 Q200.4 R210.2
VIO: C120.2 J2.1 J4.1 J101.2 R10.1 R14.2 R17.2 R107.1 R108.1 R143.1 U107.12(VL)
VSYS: C1.1 C30.1 R2.2 SW2.1 U1.E2 U1.E3 U1.E4 VSYS.1(TP1)
VUSB: C108.2 C110.2 C112.2 C118.2 C154.2 C202.1 C207.1 C212.1 FB100.2 J100.1 R115.1 U101.19 U102.1 U102.3(SHDN*) U103.1 U103.3(SHDN*) U104.1 U104.3(SHDN*) U200.8 U201.8 U202.8

Pads without a net: J6 4; SW1 2 3; U1 C1 D3; U100 5 6 7 8 9 10 11 12 13 14 15 16 17 18 19 20 21 29 30 31 32 33 34 38 45 46 47 48 57; U101 5 9 10 11 12 13 18 23 25 27 28 29; U107 4 7

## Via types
v1: diameter 0.457, hole 0.203, TOP to BOTTOM, 309 vias
v2: diameter 0.254, hole 0.102, TOP to BOTTOM, 20 vias

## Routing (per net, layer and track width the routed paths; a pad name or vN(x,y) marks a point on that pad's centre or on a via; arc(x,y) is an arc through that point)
+1.8V: length 44.6
  BOTTOM w0.381: 10.15,91.11 C111.2 10.15,90.12 10.12,90.09 U103.5 ; 10.15,91.11 9.84,91.41 7.06,91.41 6.48,90.83 R160.1 ; 10.15,91.11 26.14,91.11 27.91,92.89 37.08,92.89 37.54,92.43 44.7,92.43 J101.3
+2.5V: length 34.3
  TOP w0.381: v1(32.92,74.98) v1(21.62,74.98)
  INTERNAL3 w0.381: v1(21.62,74.98) v1(21.62,89.18)
  BOTTOM w0.254: U100.40 33.7,73.96 33.54,74.12 C151.1
  BOTTOM w0.381: v1(21.62,89.18) 19.02,89.18 18.89,89.31 C113.2 ; R156.1 18.25,90.13 C113.2 ; C113.2 18.25,88.65 17.79,88.19 U104.5 ; v1(32.92,74.98) 33.2,74.7 C151.1
+3.3V: length 240.2
  TOP w0.254: D101.A 16.85,80.91 16.89,80.95 D100.A
  TOP w0.381: 55.14,83.99 v1(49.36,83.99) 48.69,83.99 48.67,83.97 v1(43.66,83.97) ; 55.14,83.99 55.16,84 v1(55.42,84) ; 55.14,83.99 v1(60.26,83.99) ; v1(49.28,88.21) 50.4,88.21 D102.A ; v1(23.93,80.9) 19.5,80.9 19.45,80.95 D100.A ; v1(28.73,84.86) v1(23.93,84.86) ; v1(34.2,63.37) v1(23.97,63.37) ; v1(28.73,79.02) v1(31.39,79.02) v1(43.66,79.02) ; v1(65.91,69.72) v1(60.3,69.72) ; D103.A v1(43.64,81.25)
  INTERNAL3 w0.254: v1(65.1,83.99) v1(65.1,82.03) ; v1(71.98,29.9) 71.98,31.56 v1(70.92,32.61) 70.92,36.73 v1(71.73,37.54) v1(71.73,39.75)
  INTERNAL3 w0.381: v1(65.91,69.72) v1(65.91,51.64) 65.89,51.64 65.89,42.37 65.63,42.11 v1(65.63,41.17) v1(65.63,32.77) ; v1(23.93,84.86) v1(23.93,80.9) 23.93,72.16 23.94,72.15 23.94,68.56 23.94,68.55 v1(23.94,67.88) 23.94,67.21 23.97,67.18 v1(23.97,63.37) ; v1(49.28,88.21) 49.28,87.54 49.36,87.45 v1(49.36,83.99) ; v1(43.66,79.02) 43.66,81.13 ; 43.66,81.13 43.64,81.15 v1(43.64,81.25) ; 43.66,81.13 v1(43.66,83.97) 43.66,84.65 43.71,84.7 43.71,86.49 41.25,88.95 J101.1 ; J100.2 v1(55.42,84) ; v1(60.3,69.72) 60.3,74.16 60.26,74.21 v1(60.26,74.88) v1(60.26,83.99) ; v1(71.36,49.24) v1(71.36,47.91)
  BOTTOM w0.254: R283.1 64.48,83.98 64.49,83.99 ; 64.49,83.99 v1(60.26,83.99) ; 64.49,83.99 v1(65.1,83.99) ; U107.11 28.99,84.7 C115.2 v1(28.73,84.86) 28.73,85.34 C157.2 ; C221.2 65.2,84.08 v1(65.1,83.99) ; v1(71.73,37.54) 71.73,37.63 R296.1 ; v1(23.94,67.88) C150.1 25.81,67.94 26.24,67.94 27.1,68.8 U100.22 ; 60.48,74.85 60.45,74.88 v1(60.26,74.88) ; 60.48,74.85 60.26,74.85 60.22,74.81 C222.2 ; 60.48,74.85 U205.7 ; v1(65.1,83.99) 65.63,83.46 R214.2 ; R100.2 32.42,78.33 R118.2 ; v1(71.73,39.75) 71.52,39.54 R295.2 ; U100.2 v1(34.2,63.37) ; v1(65.1,82.03) 65.1,80.97 U205.13 ; R298.1 v1(71.98,29.9)
  BOTTOM w0.381: C158.2 v1(49.28,88.21) ; C158.2 48.54,88.16 U102.5 ; C158.2 48.5,88.85 48.12,89.23 45.82,89.23 45.53,88.93 R158.1 ; C115.2 v1(28.73,79.02) ; v1(43.66,79.02) 43.66,78.14 43.7,78.1 R163.2 ; R118.2 31.39,78.34 v1(31.39,79.02) ; R294.1 70.9,47.91 v1(71.36,47.91) ; v1(65.91,51.64) 66.59,51.64 66.64,51.59 69.22,51.59 70.92,49.88 R293.2 v1(71.36,49.24) ; v1(65.63,32.77) 70.09,32.77 70.24,32.61 v1(70.92,32.61) 71.47,32.06 R297.2 ; v1(65.63,41.17) 69.99,41.17 71.31,39.85 R295.2
BST: length 3.5
  INTERNAL2 w0.254: v2(49.83,39.04) 48.62,40.26 48.62,40.9 48.06,41.45 v2(47.69,41.45)
CTSN: length 26.5
  TOP w0.254: v1(14.84,68) 15.7,68 16.41,68.71 v1(24.89,68.71) ; v1(25.2,73.89) v1(32.79,73.89)
  INTERNAL3 w0.254: v1(24.89,68.71) 24.89,68.94 25.2,69.24 v1(25.2,73.89)
  BOTTOM w0.254: U101.8 v1(14.84,68) ; v1(32.79,73.89) 33.2,73.48 U100.39
DCDN: length 13.9
  TOP w0.254: v1(24.61,69.77) 24.18,69.34 16.23,69.34 15.54,68.66 v1(15.32,68.66)
  BOTTOM w0.254: U101.7 15.32,69.72 v1(15.32,68.66) ; v1(24.61,69.77) 25.04,70.21 25.17,70.21 25.27,70.3 U100.25
DSRN: length 17.9
  TOP w0.254: v1(15.84,66.51) v1(25.84,66.51)
  INTERNAL3 w0.254: v1(25.84,66.51) v1(25.84,69.48)
  BOTTOM w0.254: v1(25.84,69.48) 26.07,69.48 26.37,69.77 26.51,69.77 26.55,69.8 U100.24 ; U101.6 v1(15.84,66.51)
DTRN: length 8.7
  BOTTOM w0.254: U100.28 22.94,71.8 22.92,71.78 22.07,71.78 21.28,70.99 U101.31
EN_EXT: length 118.4
  TOP w0.254: v1(6.7,66.9) R3.1 8.31,66.9 8.35,66.94 Q1.1 ; J100.5 61.59,92.58 37.26,92.58 36.32,91.64 11.71,91.64 10.9,92.46 v1(9.02,92.46) ; J2.2 4.16,39.74 4.2,39.7 v1(5.99,39.7)
  INTERNAL3 w0.254: v1(9.02,92.46) 6.78,90.22 v1(6.78,84.05) 6.7,83.97 v1(6.7,66.9) 6.7,60.45 5.99,59.74 v1(5.99,39.7)
  BOTTOM w0.254: v1(6.78,84.05) 5.38,84.05 5.36,84.04 EN_EXT.1
GROUND: length 65.5
  TOP w0.114: U1.C3 U1.D2
  TOP w0.152: U1.C3 U1.B3 ; 47.69,40.49 U1.E5 ; v2(45.8,41.96) 45.9,41.85 U1.B1
  TOP w0.254: Q1.2 8.37,65.94 8.31,66 R3.2 ; 47.69,40.39 47.69,40.49
  TOP w0.381: C239.1 v1(85.22,49.28) ; C241.1 84.55,33.56
  TOP w0.508: v1(2,57.14) 1.11,58.03 SW2.3
  BOTTOM w0.127: R208.2 83.09,49.14 84.65,50.69 85.28,50.69 85.35,50.62 R211.2 ; R243.2 78.9,34.52 79.79,34.52 80.27,34.04 83.57,34.04 85.04,35.51 85.48,35.51 85.6,35.39 85.6,34.98 ; R233.2 85.34,42.33 85.25,42.42 84.68,42.42 83.55,41.29 80.05,41.29 79.31,42.03 R230.2
  BOTTOM w0.254: U101.17 v1(14.29,74.74) ; U205.9 U205.8 v1(61.23,80.95) ; U101.20 16.34,76.76 15.75,77.34 C108.1 v1(15.53,77.81) ; C222.1 v1(59.62,73.42) ; U100.23 26.71,69.3 v1(26.49,69.09) 26.18,68.78 C150.2 ; R210.1 v1(91.76,53.12) ; v1(63.48,72.83) 63.48,73.13 63.82,73.48 U205.4 ; U101.24 v1(19.06,74.74) ; U101.26 v1(21.26,73.49) ; C223.1 v1(66.41,71.97)
  BOTTOM w0.381: 93.31,38.85 92.94,38.48 R244.1 ; v1(46.95,83.26) C118.1 47.65,83.56 47.89,83.81 U102.2 ; R211.2 85.22,49.88 v1(85.22,49.28) ; U104.2 17.14,84.73 16.85,84.44 C112.1 ; U108.2 v1(51.78,78.35) ; C113.1 17.32,89.28 R157.2 16.54,89.28 v1(16.23,88.98) ; v1(8.39,85.26) C110.1 9.23,85.56 9.47,85.8 U103.2 ; U101.4 16.84,68.77 16.43,68.37 v1(16.43,67.7) ; v1(91.24,42.51) 91.21,42.55 R231.1 ; R1.2 7.61,90.14 7.9,90.42 ; C158.1 v1(47.1,88.21) ; v1(61.44,29.84) 61.43,29.84 ; C111.1 v1(8.29,90.43) ; R159.2 v1(46.29,88.41) ; R110.2 v1(50.38,86.52)
  BOTTOM w0.457: 6.39,72.26 J6.5
  BOTTOM w0.508: 6.39,72.26 6.41,72.26 6.53,72.14 ; C114.2 R122.2 6.85,72.12
  vias: v1(2.55,44.65) v1(3.15,55.07) v1(3.25,67.97) v1(21.2,93.86) v1(21.78,93.85) v1(23.46,32.9) v1(24.04,32.89) v1(24.68,47.02) v1(25.26,47.01) v1(29.74,22.1) v1(30.24,52.76) v1(30.31,22.1) v1(30.82,52.75) v1(42.69,40.44) v1(42.69,39.84) v1(42.72,39.2) v1(43.27,40.44) v1(43.29,39.83) v1(43.29,39.19) v1(45.34,14.2) v1(45.41,81.84) v1(45.38,16.82) v1(45.38,15.65) v1(45.92,64.09) v1(45.86,47.49) v1(45.86,46.89) v1(45.88,46.25) v1(45.98,81.84) v1(46.49,64.08) v1(46.47,47.51) v1(46.48,46.87) v1(46.45,46.27) v1(46.53,18.19) v1(46.57,16.86) v1(46.58,15.6) v1(46.62,14.27) v1(47.44,34.22) v1(47.84,18.18) v1(47.84,16.91) v1(48.01,34.21) v1(48.69,39.34) v1(49,38.94) v1(49.18,47.49) v1(49.18,46.89) v1(49.17,46.27) v1(49.79,47.51) v1(49.8,46.87) v1(49.77,46.27) v1(50.06,39.7) v1(50.57,42.19) v1(51,42.42) v1(51.15,81.67) v1(51.72,81.66) v1(53.41,14.79) v1(53.59,74) v1(53.98,14.78) v1(54.16,73.99) v1(58.57,42.11) v1(60.81,49.94) v1(60.78,40.64) v1(63.68,50.47) v1(64.47,40.74) v1(64.92,34.44) v1(65.1,29.03) v1(65.13,26.39) v1(65.23,50.8) v1(65.23,49.68) v1(68.25,44.4) v1(68.44,43.22) v1(68.42,41.89) v1(68.73,34.54) v1(68.91,26.44) v1(69.65,41.89) v1(69.67,43.22) v1(70.82,41.66) v1(71.34,78.01) v1(71.32,41.05) v1(71.7,15.5) v1(71.83,40.64) v1(71.83,33.17) v1(71.92,78) v1(71.97,57.21) v1(72.27,15.49) v1(73.21,57.21) v1(73.99,33.5) v1(74.47,41.15) v1(74.75,33.5) v1(74.88,49.28) v1(74.98,41.66) v1(75.13,35.69) v1(75.13,34.87) v1(75.13,34.11) v1(75.29,50.5) v1(75.29,49.78) v1(75.29,42.27) v1(80.05,15.5) v1(80.63,15.49) v1(81.45,89.16) v1(81.48,61.26) v1(81.58,57.71) v1(81.58,53.75) v1(81.66,40.51) v1(82.02,89.15) v1(85.85,49.28) v1(85.98,49.91) v1(85.98,42.24) v1(85.98,41.63) v1(86.23,35.05) v1(86.23,34.42) v1(86.66,54.05) v1(91.53,85.32) v1(92.11,85.32) v1(93.34,38.89) v1(93.98,47.96) v1(93.98,38.91)
ISET_SBB0: length 31.4
  INTERNAL3 w0.254: v1(65.12,73.29) 65.12,52.89 65.1,52.86 v1(65.1,52.63) ; v1(59.87,53.11) 59.87,52.15 59.88,52.13 v1(59.88,50)
  BOTTOM w0.254: R203.1 v1(59.88,50) ; v1(59.87,53.11) 64.62,53.11 v1(65.1,52.63) ; U205.2 v1(65.12,73.29)
ISET_SBB1: length 40.6
  INTERNAL3 w0.254: v1(64.47,42.24) 64.47,42.54 64.47,42.55 v1(64.47,72.55) ; v1(59.92,39.75) v1(59.92,42.24)
  BOTTOM w0.254: U205.3 v1(64.47,72.55) ; v1(59.92,42.24) v1(64.47,42.24) ; v1(59.92,39.75) 59.92,38.83 R224.1
ISET_SBB2: length 47.4
  INTERNAL3 w0.254: v1(62.74,73.11) 62.74,33.66 59.74,30.66 v1(58.88,30.66)
  BOTTOM w0.254: v1(62.74,73.11) 63.17,73.54 U205.5 ; R237.1 59.78,30.66 v1(58.88,30.66)
LXA: length 3.2
  INTERNAL2 w0.254: 47.29,40.58 v2(47.29,41.05)
  INTERNAL2 w0.508: 47.29,40.58 47.29,38.83 46.94,38.48 46.94,38.15 v2(46.81,38.02)
  vias: v2(46.81,37.69) v2(47.11,38.02) v2(47.11,37.69)
LXB: length 5
  TOP w0.381: C4.2 49.86,38.07 49.48,37.69 v2(48.44,37.69) L1.1
  INTERNAL2 w0.254: 48.05,40.69 v2(47.69,41.05)
  INTERNAL2 w0.508: v2(48.43,38.02) 48.25,38.2 48.25,38.7 48.05,38.89 48.05,40.69
  vias: v2(48.14,38.03) v2(48.14,37.69)
MAXQP03: length 3.5
  BOTTOM w0.254: U100.52 37.34,67.3 37.4,67.36 PO3.1
MAXQP05: length 3.8
  BOTTOM w0.254: PO5.1 37.51,65.47 36.68,66.3 36.32,66.3 36.31,66.3 U100.54
NEN: length 81.4
  TOP w0.152: U1.A2 45.36,43.38 22.25,43.38 20.02,45.62 v1(19.41,45.62) ; v1(9.47,32.07) 8.92,32.07 8.87,32.12 J2.5
  TOP w0.254: v1(9.52,59.61) 10.13,59.61 10.16,59.64 10.87,59.64 11.3,60.06 J5.2 ; v1(19.41,45.62) v1(9.45,45.62)
  INTERNAL3 w0.152: v1(9.52,59.61) 9.52,45.72 ; 9.52,45.72 9.52,32.68 9.47,32.63 v1(9.47,32.07) ; 9.52,45.72 9.45,45.65 v1(9.45,45.62) ; v1(19.41,45.62) 19.41,46.28 19.47,46.34 NEN.1
NIRQ: length 111.3
  TOP w0.127: v2(45.67,41.45) 45.39,41.45
  TOP w0.152: v1(13.24,41.14) v1(27.74,41.14) 39.12,41.14 39.12,41.15 40.87,41.15 41.17,41.45 45.39,41.45 ; NIRQ.1 9.54,29.58 J2.6
  INTERNAL2 w0.127: v2(46.47,41.45) v2(45.67,41.45)
  INTERNAL3 w0.152: NIRQ.1 13.24,33.28 v1(13.24,41.14)
  INTERNAL3 w0.254: v1(27.74,41.14) v1(27.74,90.96)
  BOTTOM w0.254: v1(27.74,90.96) 33.32,90.96 33.96,90.32 33.96,89.85 33.95,89.84 R150.2 33.96,89.27 R14.1
NIRQ1: length 18.3
  INTERNAL3 w0.254: v1(37.62,80.37) 37.62,71.24 37.65,71.22 PO0.1
  BOTTOM w0.254: U100.49 35.93,68.8 PO0.1 ; v1(37.62,80.37) 37.01,80.37 36.99,80.35 R152.1
NRST: length 67.7
  TOP w0.152: v2(45.26,42.39) v1(14.66,42.39)
  TOP w0.254: 9.55,27.04 9.54,27.05 R10.2 ; 9.55,27.04 J2.7 ; 9.55,27.04 10.74,27.04 10.8,27.09 NRST.1 14.03,27.09 14.05,27.11 v1(14.66,27.11)
  INTERNAL2 w0.152: v2(46.49,41.85) 46.17,42.18 46.17,42.22 46,42.39 v2(45.26,42.39)
  INTERNAL3 w0.254: J8.1 13.93,43.11 v1(14.66,42.39) 14.66,41.78 14.66,41.78 14.66,27.72 14.66,27.72 v1(14.66,27.11)
P01: length 4.1
  BOTTOM w0.254: U100.50 36.7,68.3 38.19,69.8 PO1.1
P02: length 2.4
  BOTTOM w0.254: PO2.1 37.17,67.8 U100.51
P04: length 2.4
  BOTTOM w0.254: PO4.1 37.36,66.8 U100.53
P06: length 2.8
  BOTTOM w0.254: PO6.1 37.6,64.85 37.29,64.85 36.33,65.8 U100.55
P07: length 4.1
  BOTTOM w0.254: U100.56 35.75,65.3 37.27,63.78 PO7.1
PWRHLD: length 105.2
  TOP w0.152: v1(10.67,42.47) 10.85,42.47 10.87,42.49 12.48,42.49 14.05,44.06 PWRHLD.1 20.67,42.88 45.47,42.88 U1.A1 ; J2.4 v1(10.66,34.66)
  TOP w0.254: v1(10.82,56.75) 11.43,56.75 11.45,56.77 R16.1
  INTERNAL3 w0.152: v1(10.82,56.75) 10.82,56.19 10.67,56.03 v1(10.67,42.47) 10.67,34.75 10.66,34.74 v1(10.66,34.66)
  INTERNAL3 w0.254: J4.2 v1(26.63,34.64)
  BOTTOM w0.254: v1(10.66,34.66) 11.27,34.66 11.28,34.64 v1(26.63,34.64)
RIN: length 16
  INTERNAL3 w0.254: v1(23.34,67.21) v1(23.34,71.3)
  BOTTOM w0.254: U100.27 23.96,71.3 23.95,71.3 v1(23.34,71.3) ; v1(23.34,67.21) 18.62,67.21 17.34,68.49 U101.3
RTSN: length 8.5
  BOTTOM w0.254: U101.32 24.39,70.49 24.69,70.79 24.73,70.79 24.74,70.8 U100.26
RXD: length 28.3
  TOP w0.254: v1(35.45,74.46) v1(20.64,74.46)
  INTERNAL3 w0.254: v1(20.64,74.46) 20.64,68.12 20.65,68.11 v1(20.65,67.82)
  BOTTOM w0.254: v1(20.65,67.82) 18.82,67.82 17.84,68.8 U101.2 ; U100.43 v1(35.45,74.46)
SBB0: length 39.7
  TOP w0.152: 48.27,41.45 U1.C6
  TOP w0.254: 48.64,41.66 48.44,41.45 48.27,41.45
  TOP w0.381: 49.5,42.93 49.16,42.58 C9.2 48.64,41.66 48.64,41.66
  TOP w0.635: 49.95,43.38 49.5,42.93
  TOP w1.27: 80.49,46.08 SBB0.1 57.04,46.06 52.64,46.06 49.95,43.38 ; J201.2 80.53,46.11
SBB1: length 39.1
  TOP w0.152: 48.27,41.05 U1.D6
  TOP w0.254: 48.86,41.05 48.27,41.05
  TOP w0.381: v1(49.18,41.25) 49.17,41.25 48.97,41.05 48.86,41.05
  TOP w0.508: v1(51.03,41.25) 53.44,41.25 53.64,41.05
  TOP w1.27: J203.2 85.8,38.93 ; 53.64,41.05 56.11,41.05 58.41,38.74 SBB1.1 83.88,38.74 84.05,38.91 85.81,38.91
  BOTTOM w0.508: v1(49.18,41.25) v1(51.03,41.25)
SBB2: length 43.1
  TOP w0.152: U1.E6 48.1,40.65 48.23,40.52
  TOP w0.254: 49.05,40.28 48.62,40.28 48.55,40.21 48.23,40.52
  TOP w0.508: 53.21,39.12 52.18,40.15 51.93,40.15 51.79,40.28 v1(51.05,40.28)
  TOP w1.27: 85.87,31.59 84.11,31.59 84.07,31.55 SBB2.1 ; 53.21,39.12 60.78,31.55 SBB2.1 ; 78.37,31.54 SBB2.1 ; J205.2 84.26,31.44
  BOTTOM w0.508: v1(51.05,40.28) 50.32,40.28 50.22,40.39 v1(49.18,40.39)
SCL: length 131
  TOP w0.127: 45.57,45.36 47.29,43.64 v2(47.29,42.67)
  TOP w0.152: v1(16.1,24.5) 15.49,24.5 15.49,24.5 J2.8 ; v1(16.05,48.26) 20.29,48.26 23.19,45.36 45.57,45.36
  TOP w0.254: v1(16.24,61.73) 18.12,61.73 18.17,61.69 SCL.1 20.53,61.69 20.56,61.72 v1(21.82,61.72)
  INTERNAL2 w0.152: v2(47.29,42.67) v2(47.29,41.85)
  INTERNAL3 w0.152: v1(16.24,61.73) 16.24,61.13 16.1,60.99 16.1,48.51 ; 16.1,48.51 v1(16.1,24.5) ; 16.1,48.51 16.05,48.46 v1(16.05,48.26)
  INTERNAL3 w0.254: v1(21.82,61.72) 21.82,72.82 22.35,73.36 v1(22.35,89.94)
  BOTTOM w0.254: v1(22.35,89.94) 22.96,89.94 22.99,89.97 31.85,89.97 32.16,89.65 R136.2 32.17,89.27 R107.2
SCL1: length 60.3
  TOP w0.254: v1(30.86,76.79) v1(58,76.79)
  INTERNAL3 w0.254: J100.3 57.96,92.77 58.01,92.73 v1(58.01,82.44) v1(58.01,79.33) 58.01,78.72 58,78.72 v1(58,76.79)
  BOTTOM w0.203: R305.1 v1(58.01,82.44)
  BOTTOM w0.254: v1(30.86,76.79) R155.2 31.41,77.42 R118.1 30.93,77.43 30.61,77.75 30.61,81.18 31.33,81.9 U107.9 ; R162.1 v1(58.01,79.33)
SDA: length 126.6
  TOP w0.127: U1.A3 46.87,42.25 46.76,42.36 46.76,42.36 45.34,43.79 44.55,43.79
  TOP w0.152: v1(16.97,56.2) 18.35,56.2 18.36,56.19 SDA.1 ; J2.9 3.76,22.81 16.38,22.81 16.41,22.84 v1(16.97,22.84) ; 44.55,43.79 23.06,43.79 20.35,46.51 v1(16.97,46.51)
  TOP w0.254: v1(22.45,56.24) 20.72,56.24 20.67,56.19 SDA.1
  INTERNAL3 w0.152: v1(16.97,22.84) v1(16.97,46.51) v1(16.97,56.2)
  INTERNAL3 w0.254: v1(23.01,89.27) 23.01,88.66 22.94,88.58 22.94,73.05 22.45,72.57 v1(22.45,56.24)
  BOTTOM w0.254: R135.2 30.51,89.28 R108.2 v1(23.01,89.27)
SDA1: length 57.9
  TOP w0.254: v1(61.7,83.3) 61.1,83.3 61.03,83.37 v1(54.34,83.37) ; v1(54.34,77.46) v1(33.09,77.46) v1(30.01,77.46)
  INTERNAL3 w0.254: J100.4 60.5,86.34 61.7,85.14 61.7,83.92 61.7,83.91 v1(61.7,83.3) ; v1(54.34,77.46) v1(54.34,83.37)
  BOTTOM w0.203: R306.1 v1(61.7,83.3)
  BOTTOM w0.254: R164.2 53.75,77.46 v1(54.34,77.46) ; v1(30.01,77.46) 30.01,83.12 30.23,83.34 U107.10 ; R148.2 32.45,77.46 R100.1 v1(33.09,77.46)
TXD: length 20.3
  TOP w0.254: v1(21.36,72.06) 36.88,72.06 36.91,72.03 v1(37.16,72.03)
  BOTTOM w0.254: U101.30 20.79,71.49 v1(21.36,72.06) ; v1(37.16,72.03) 36.43,71.3 U100.44
UNNAMED_1_CL-SB-12B-1X_I99_2: length 3.3
  TOP w0.254: SW2.2 7.4,61.54 7.5,61.64 J5.1
UNNAMED_1_EKCAPNP_I69_2: length 23.5
  TOP w0.254: R17.1 45.41,44.42 v1(46.74,43.09)
  INTERNAL2 w0.102: v2(47.29,41.45) 46.74,42.01 46.74,42.21
  INTERNAL2 w0.127: 46.74,42.21 46.74,42.37
  INTERNAL2 w0.254: 46.74,42.37 v1(46.74,43.09)
  BOTTOM w0.254: C12.2 v1(46.74,43.09)
UNNAMED_1_EVQ-Q2XXXX_I7_1: length 20.4
  TOP w0.254: Q1.3 11.71,66.44 13.84,64.32 J5.3 13.84,60.39 13.95,60.27 R2.1
  TOP w0.381: v1(11.63,54.05) 9.35,54.05 SW1.1
  INTERNAL3 w0.254: J5.3 13.84,60.39 13.79,60.34 13.79,59.77 11.63,57.61 v1(11.63,54.05)
UNNAMED_1_HEADER2P_I92_2: length 3.7
  TOP w0.254: J8.2 13.93,54.35 13.96,54.37 R16.2
UNNAMED_4_10103592-0001LF_I2_1: length 5.1
  BOTTOM w0.381: C155.1 7.11,77.88 7.11,77.26 7.44,76.93 FB100.1
  BOTTOM w0.457: FB100.1 7.44,75.67 6.63,74.86 J6.1
UNNAMED_4_10103592-0001LF_I2_2: length 4.9
  BOTTOM w0.254: R123.1 9.31,74.19 9.29,74.21 J6.2
UNNAMED_4_10103592-0001LF_I2_3: length 5
  BOTTOM w0.254: J6.3 9.05,73.56 9.33,73.28 R103.1
UNNAMED_4_10103592-0001LF_I2_SHIELD10: length 19.5
  BOTTOM w0.508: J6.8 3.78,75.98 J6.9 1.91,77.46 J6.10 J6.11 2.11,72.42 J6.6 3.78,71.13 J6.7 5.54,70.78 R122.1 7.46,70.64 R142.1
UNNAMED_4_CAPNP_I101_2: length 8.8
  BOTTOM w0.254: U100.41 34.2,78.5 34.89,79.19 C153.2 36.71,79.19 Y101.3
UNNAMED_4_CAPNP_I105_2: length 8.5
  BOTTOM w0.254: U100.42 34.7,74.75 35.03,75.08 37.85,75.08 38.37,75.6 C152.2 38.95,76.85 Y101.1
UNNAMED_4_EKCAPNP_I12_1: length 18.5
  TOP w0.254: v1(13.23,74.8) 14.1,75.67 v1(19.95,75.67)
  INTERNAL3 w0.254: v1(19.95,69.87) v1(19.95,75.67)
  BOTTOM w0.254: v1(13.23,74.8) 12.28,74.8 C156.2 12.31,74.78 13.1,73.99 U101.16 ; 19.95,69.74 v1(19.95,69.87) ; 19.95,69.74 U101.1 ; 19.95,69.74 20.05,69.63 C159.1
UNNAMED_4_EKCAPNP_I29_1: length 1.3
  BOTTOM w0.508: C114.1 8.8,70.71 R142.2
UNNAMED_4_EKRESSMD_I15_2: length 3.6
  BOTTOM w0.254: U101.15 12.36,73.49 11.66,74.19 R123.2
UNNAMED_4_EKRESSMD_I16_2: length 3.4
  BOTTOM w0.254: R103.2 10.84,73.3 11.43,73.3 11.75,72.99 U101.14
UNNAMED_4_EKRESSMD_I17_1: length 1.8
  BOTTOM w0.254: R111.1 17.34,76.09 U101.22
UNNAMED_4_EKRESSMD_I17_2: length 2.2
  TOP w0.254: D100.K 18.01,78.67 v1(18.01,78.11)
  BOTTOM w0.254: R111.2 17.64,77.33 18.01,77.7 v1(18.01,78.11)
UNNAMED_4_EKRESSMD_I18_1: length 1.7
  BOTTOM w0.254: R109.1 16.83,75.84 16.84,75.83 U101.21
UNNAMED_4_EKRESSMD_I18_2: length 2.2
  TOP w0.254: D101.K 16.31,78.75 v1(16.31,78.11)
  BOTTOM w0.254: v1(16.31,78.11) 16.31,77.79 16.78,77.32 R109.2
UNNAMED_4_EKRESSMD_I87_1: length 2.2
  BOTTOM w0.254: U107.3 32.93,86.97 33.95,87.99 R150.1
UNNAMED_4_EKRESSMD_I109_1: length 3.5
  BOTTOM w0.254: U100.36 31.7,75.04 31.41,75.33 R155.1
UNNAMED_4_EKRESSMD_I113_1: length 3.4
  BOTTOM w0.254: U100.37 32.2,75.03 32.45,75.28 R148.1
UNNAMED_4_EKRESSMD_I153_1: length 1.8
  BOTTOM w0.254: R135.1 31.34,87.8 31.33,87.79 U107.1
UNNAMED_4_EKRESSMD_I154_1: length 1.8
  BOTTOM w0.254: U107.2 32.13,87.75 32.16,87.78 R136.1
UNNAMED_4_EKRESSMD_I171_2: length 1.7
  BOTTOM w0.381: U107.6 35.07,83.9 35.08,83.91 R143.2
UNNAMED_4_EKRESSMD_I174_1: length 4.6
  BOTTOM w0.381: U104.4 15.87,87.93 15.57,88.24 15.57,89.91 15.84,90.18 R157.1 17.31,90.18 R156.2
UNNAMED_4_EKRESSMD_I177_1: length 1.7
  BOTTOM w0.381: U102.4 47.23,87 R159.1 45.53,87 R158.2
UNNAMED_4_EKRESSMD_I190_2: length 2.6
  BOTTOM w0.254: U107.8 32.13,81.85 32.12,81.83 R152.2
  BOTTOM w0.381: R161.2 R152.2
UNNAMED_4_LED_I7_B: length 1.8
  TOP w0.381: D102.K v1(52.22,87.25)
  BOTTOM w0.381: v1(52.22,87.25) 52.22,86.76 R110.1
